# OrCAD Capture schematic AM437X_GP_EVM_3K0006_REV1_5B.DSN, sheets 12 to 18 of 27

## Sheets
12 Pg14: Camera #0: size C; rev: 1.5A
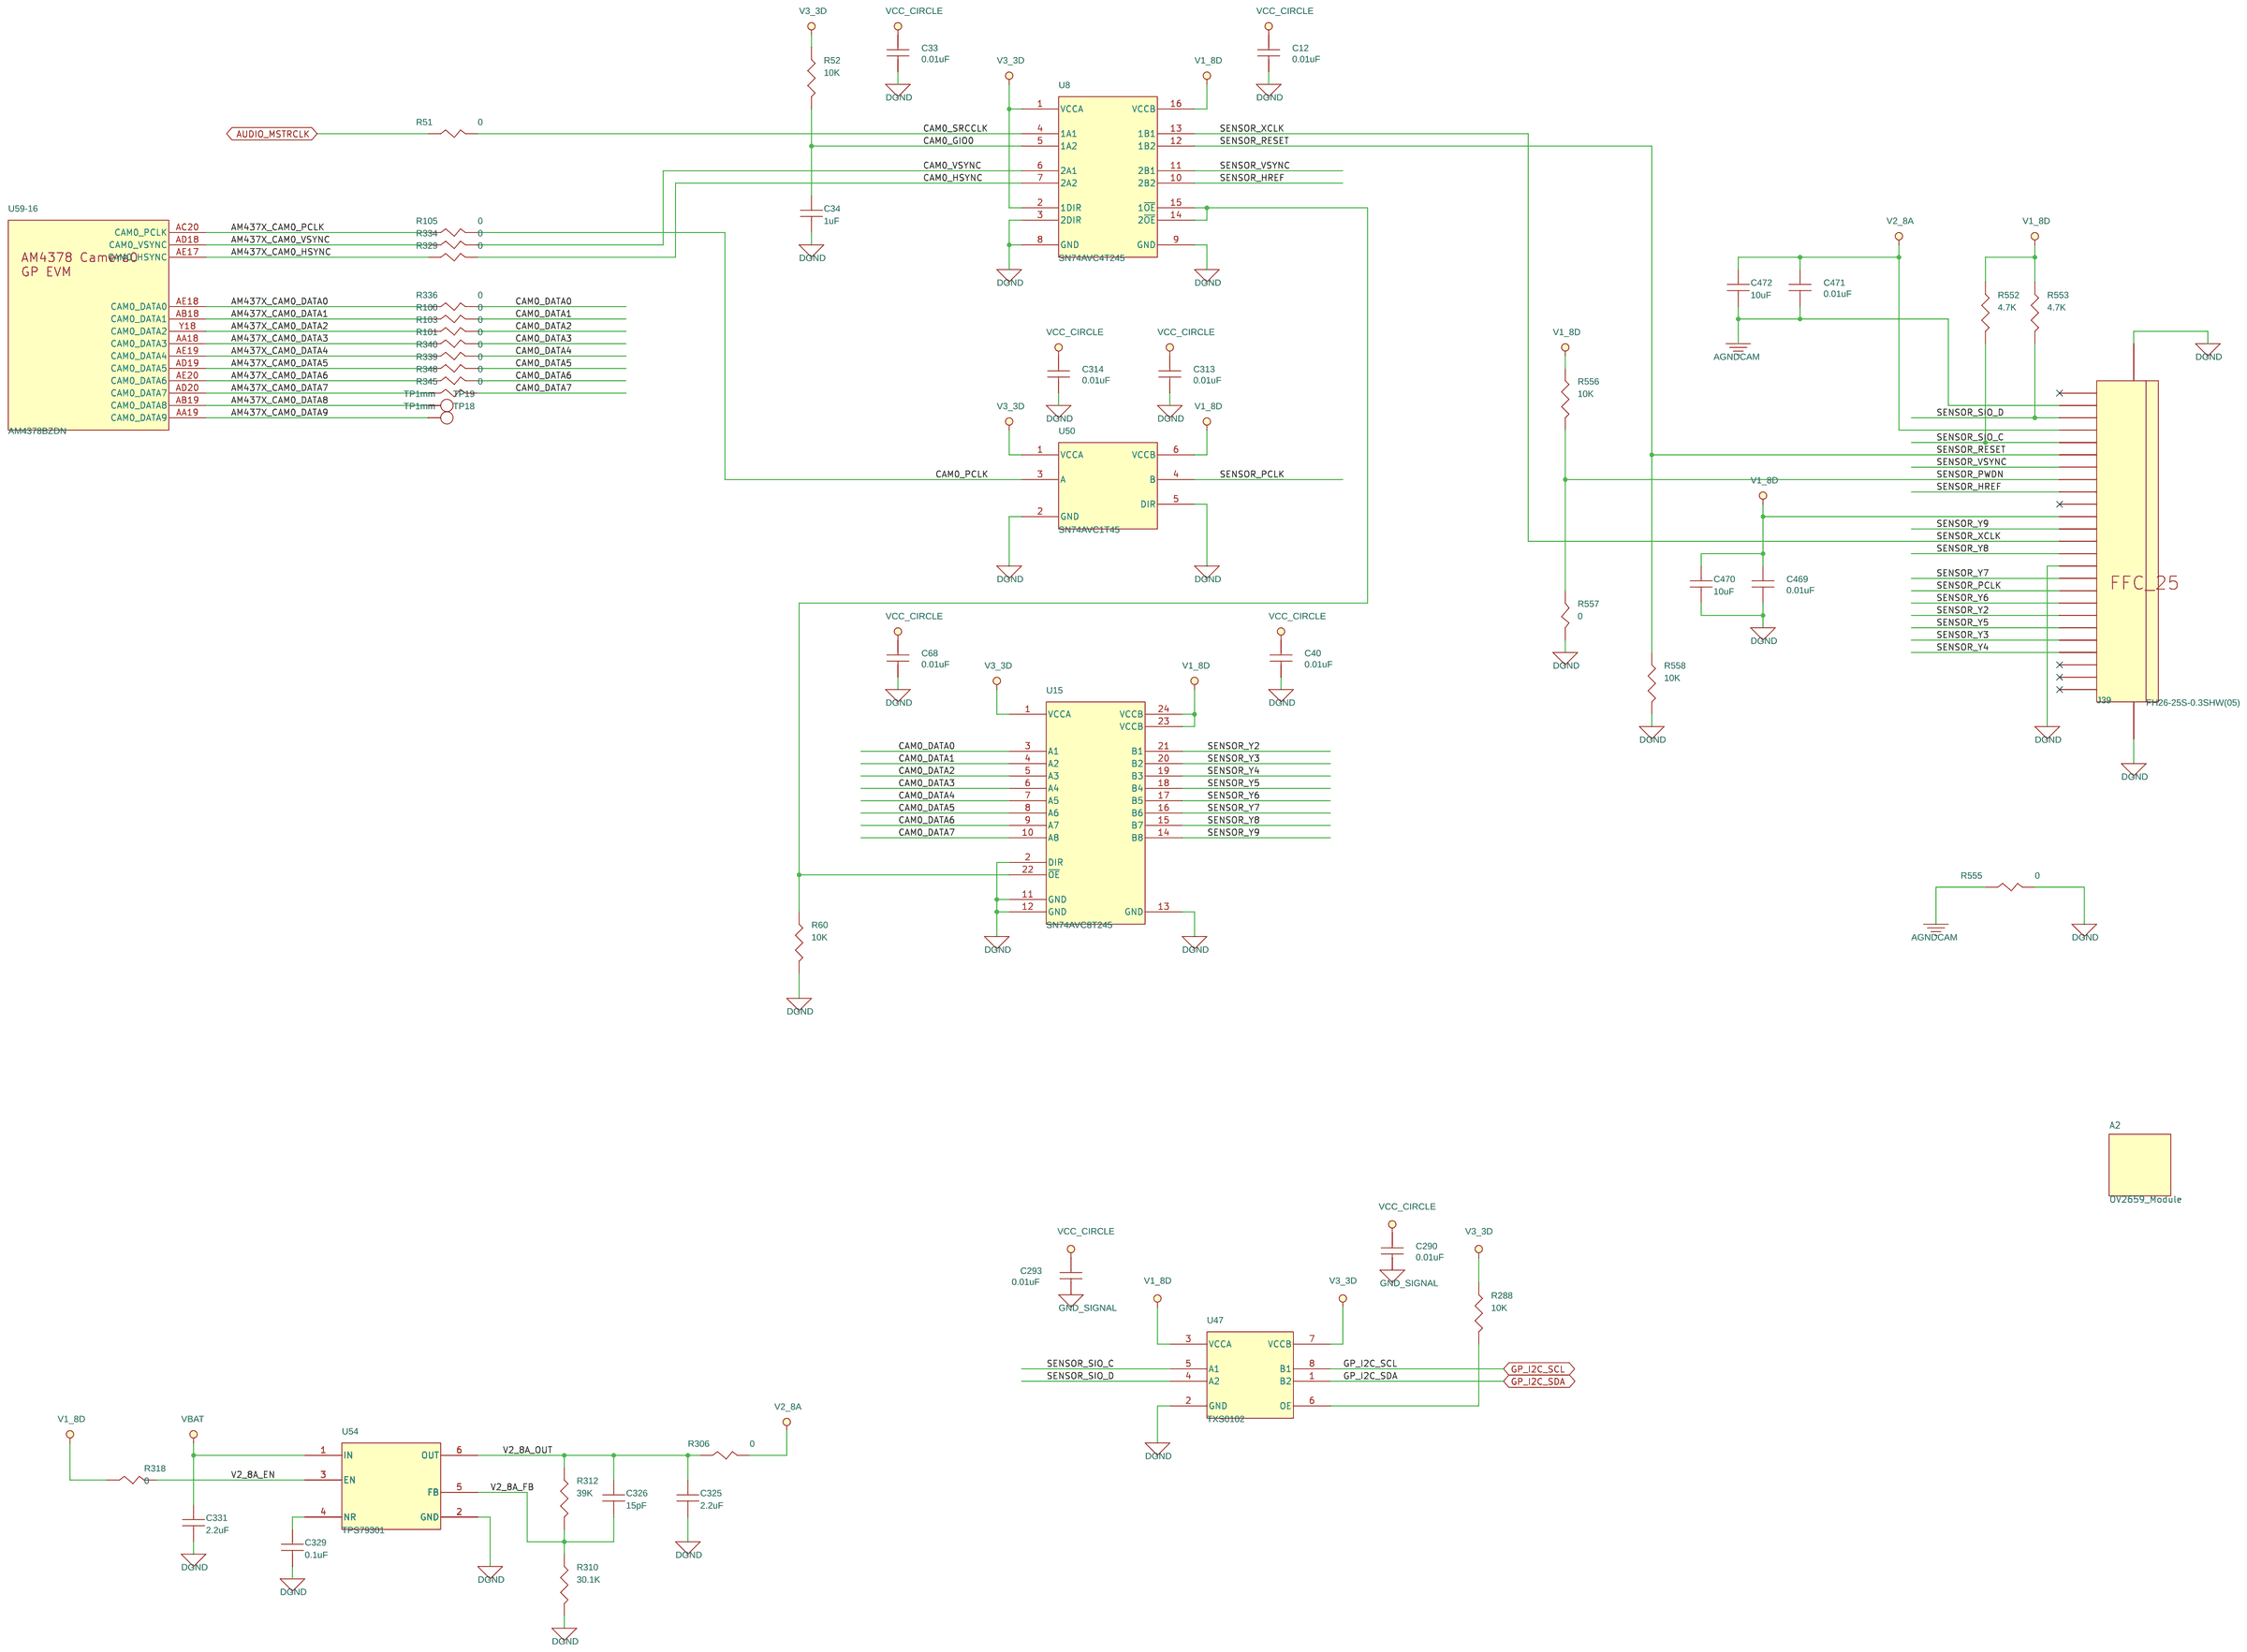
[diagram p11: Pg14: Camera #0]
13 Pg01: Title Page: note: Preliminary
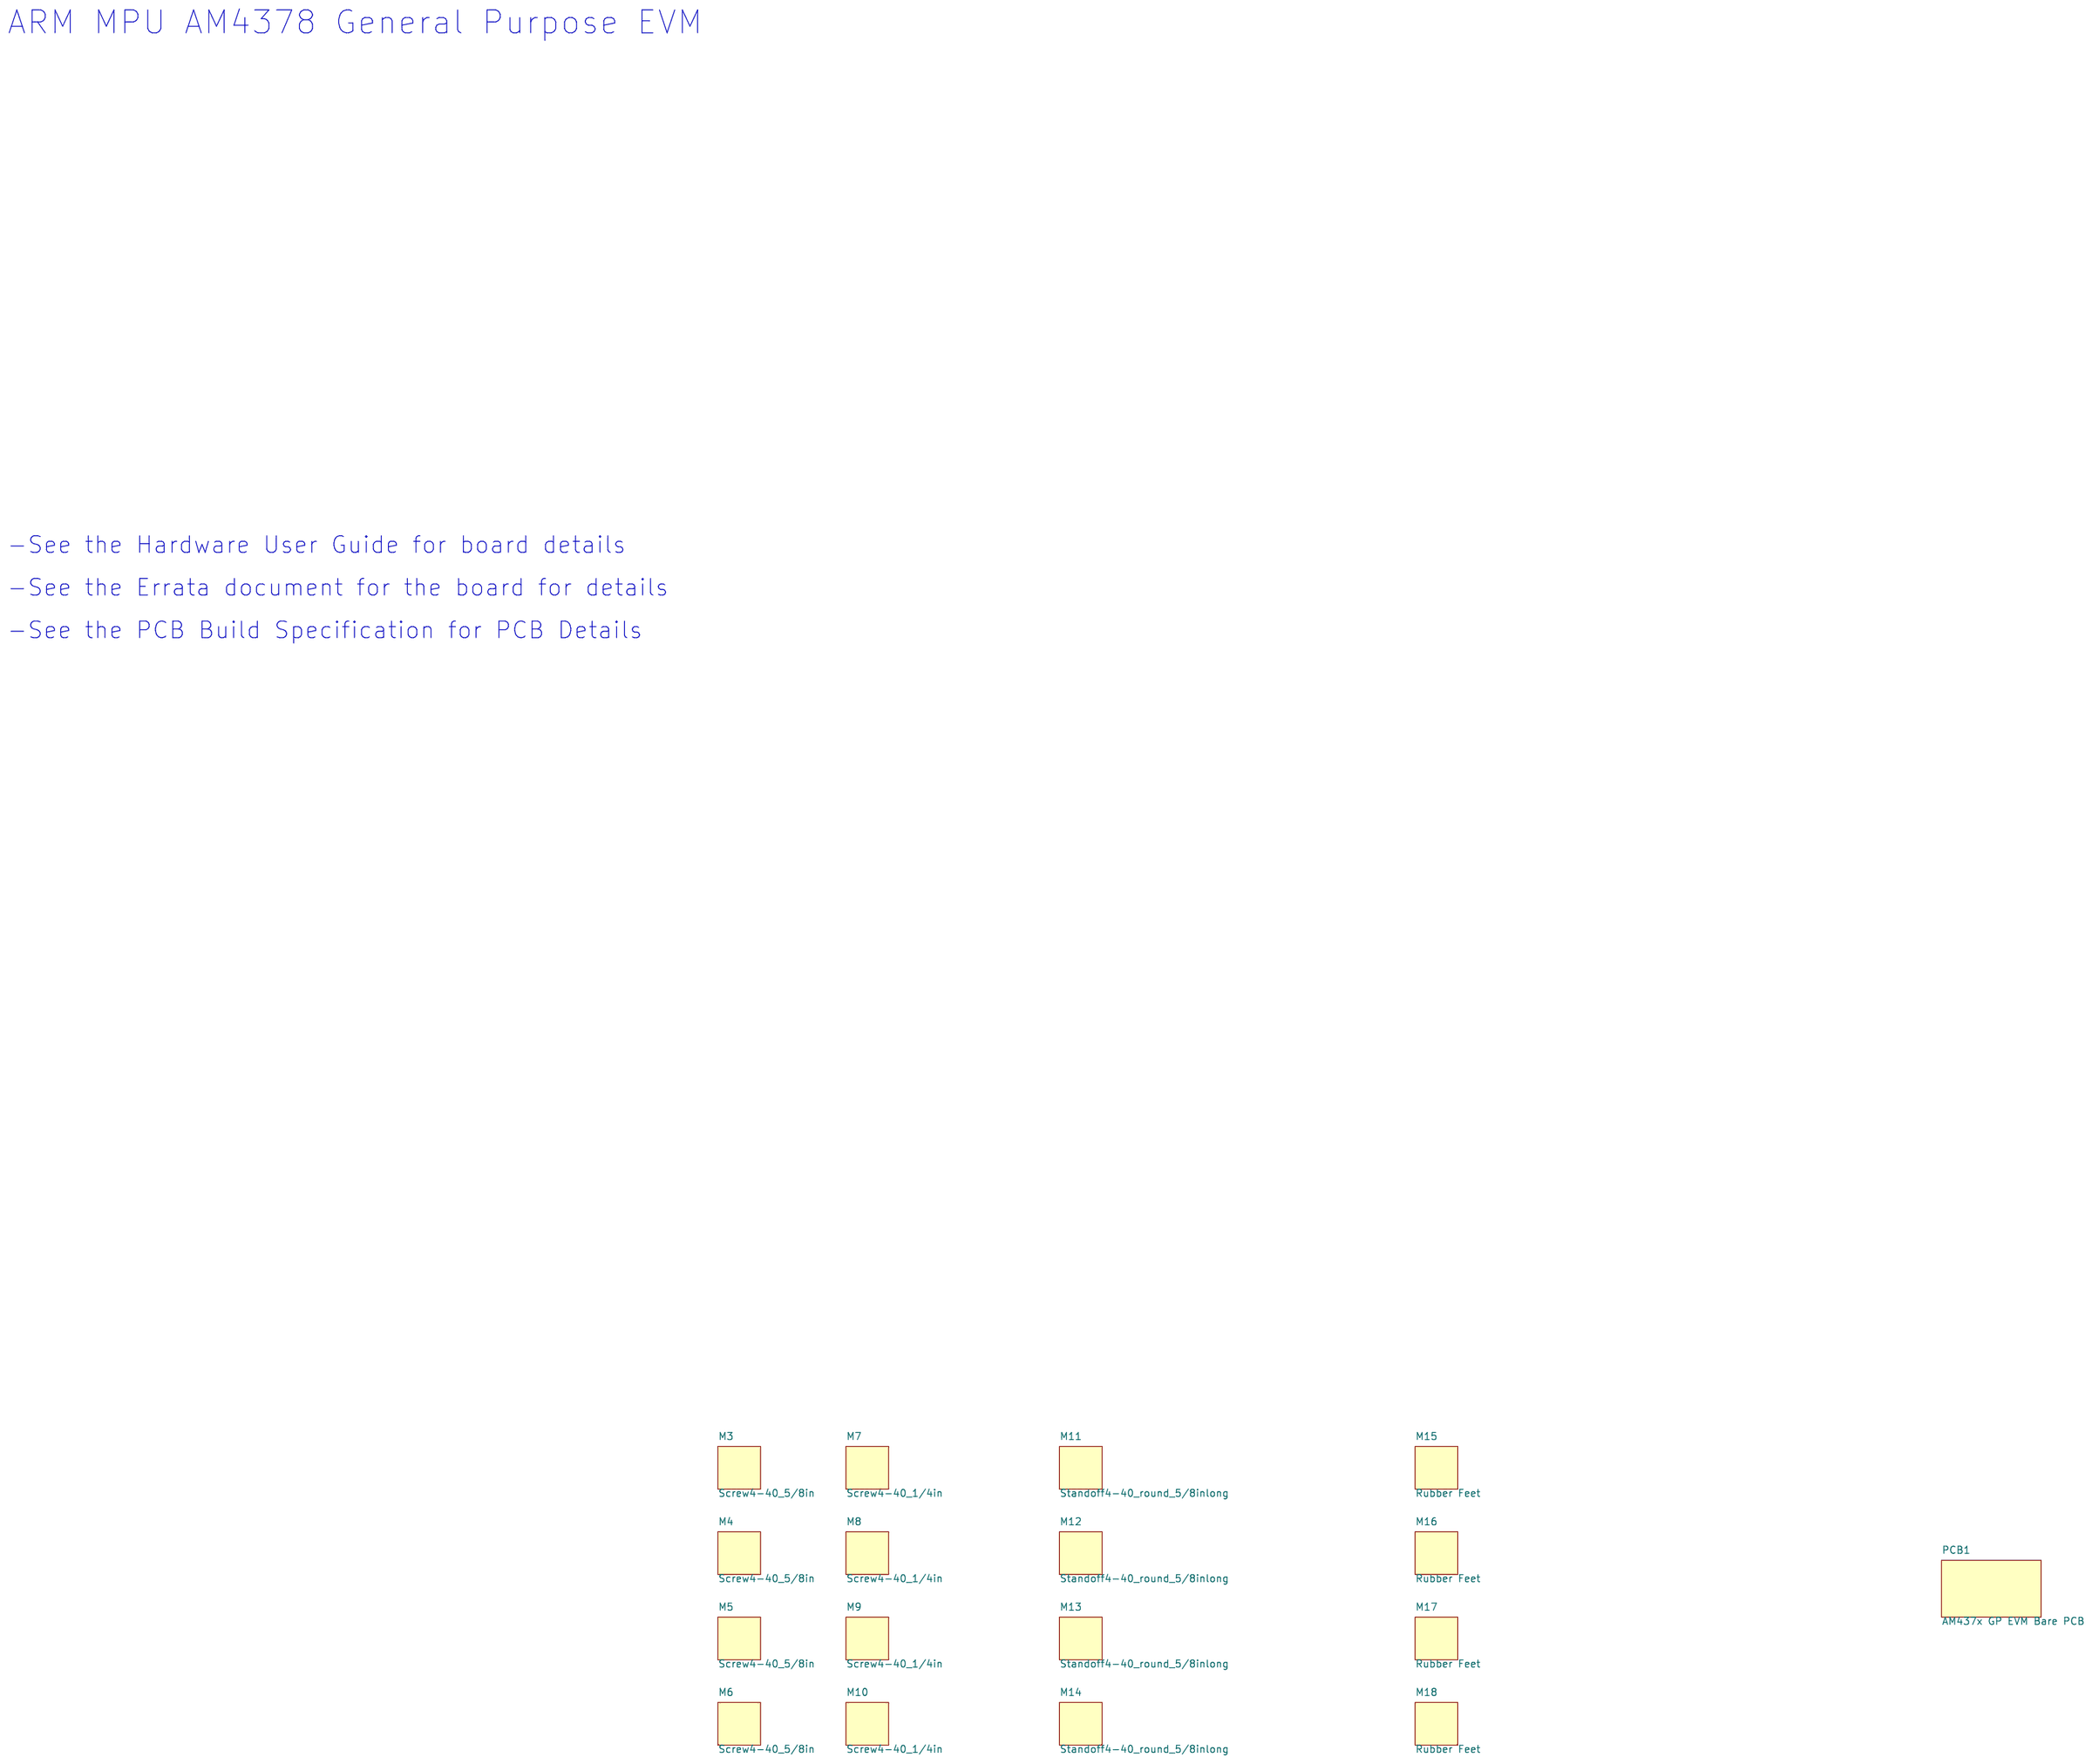
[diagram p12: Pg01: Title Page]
14 Pg07: Ethernet #1: size C
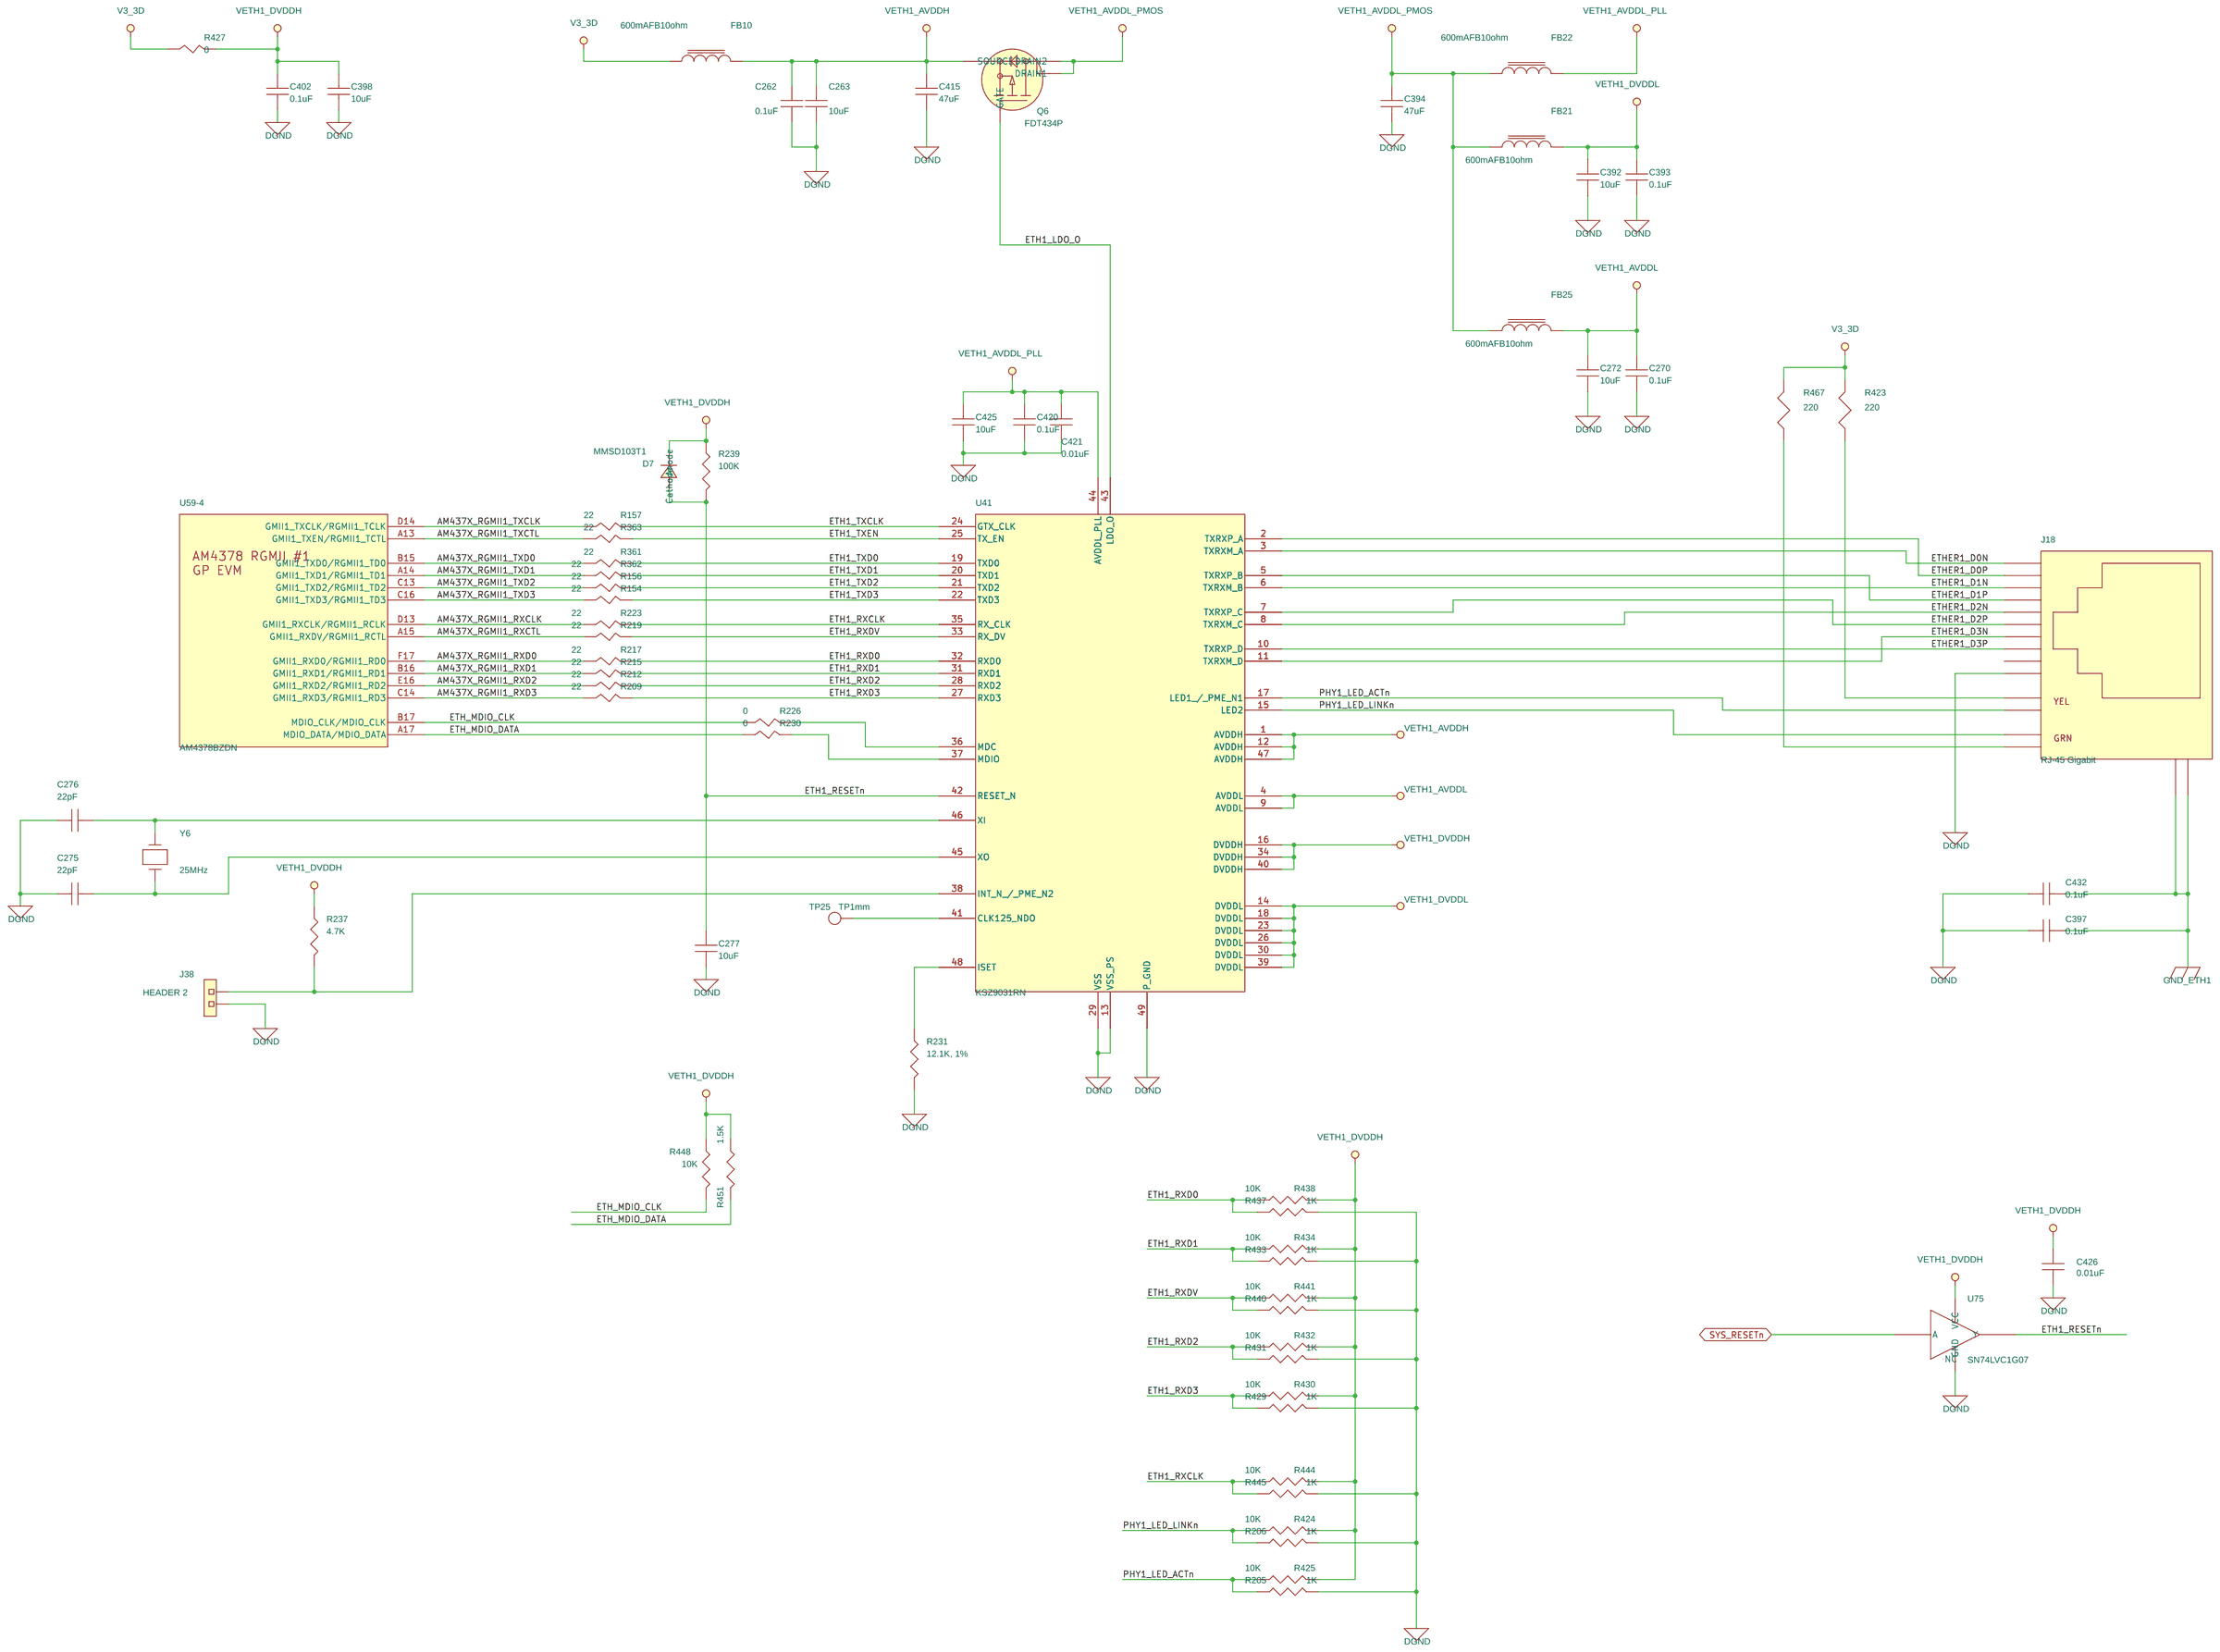
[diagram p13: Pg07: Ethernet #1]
15 Pg06: DDR3 Memory: size C
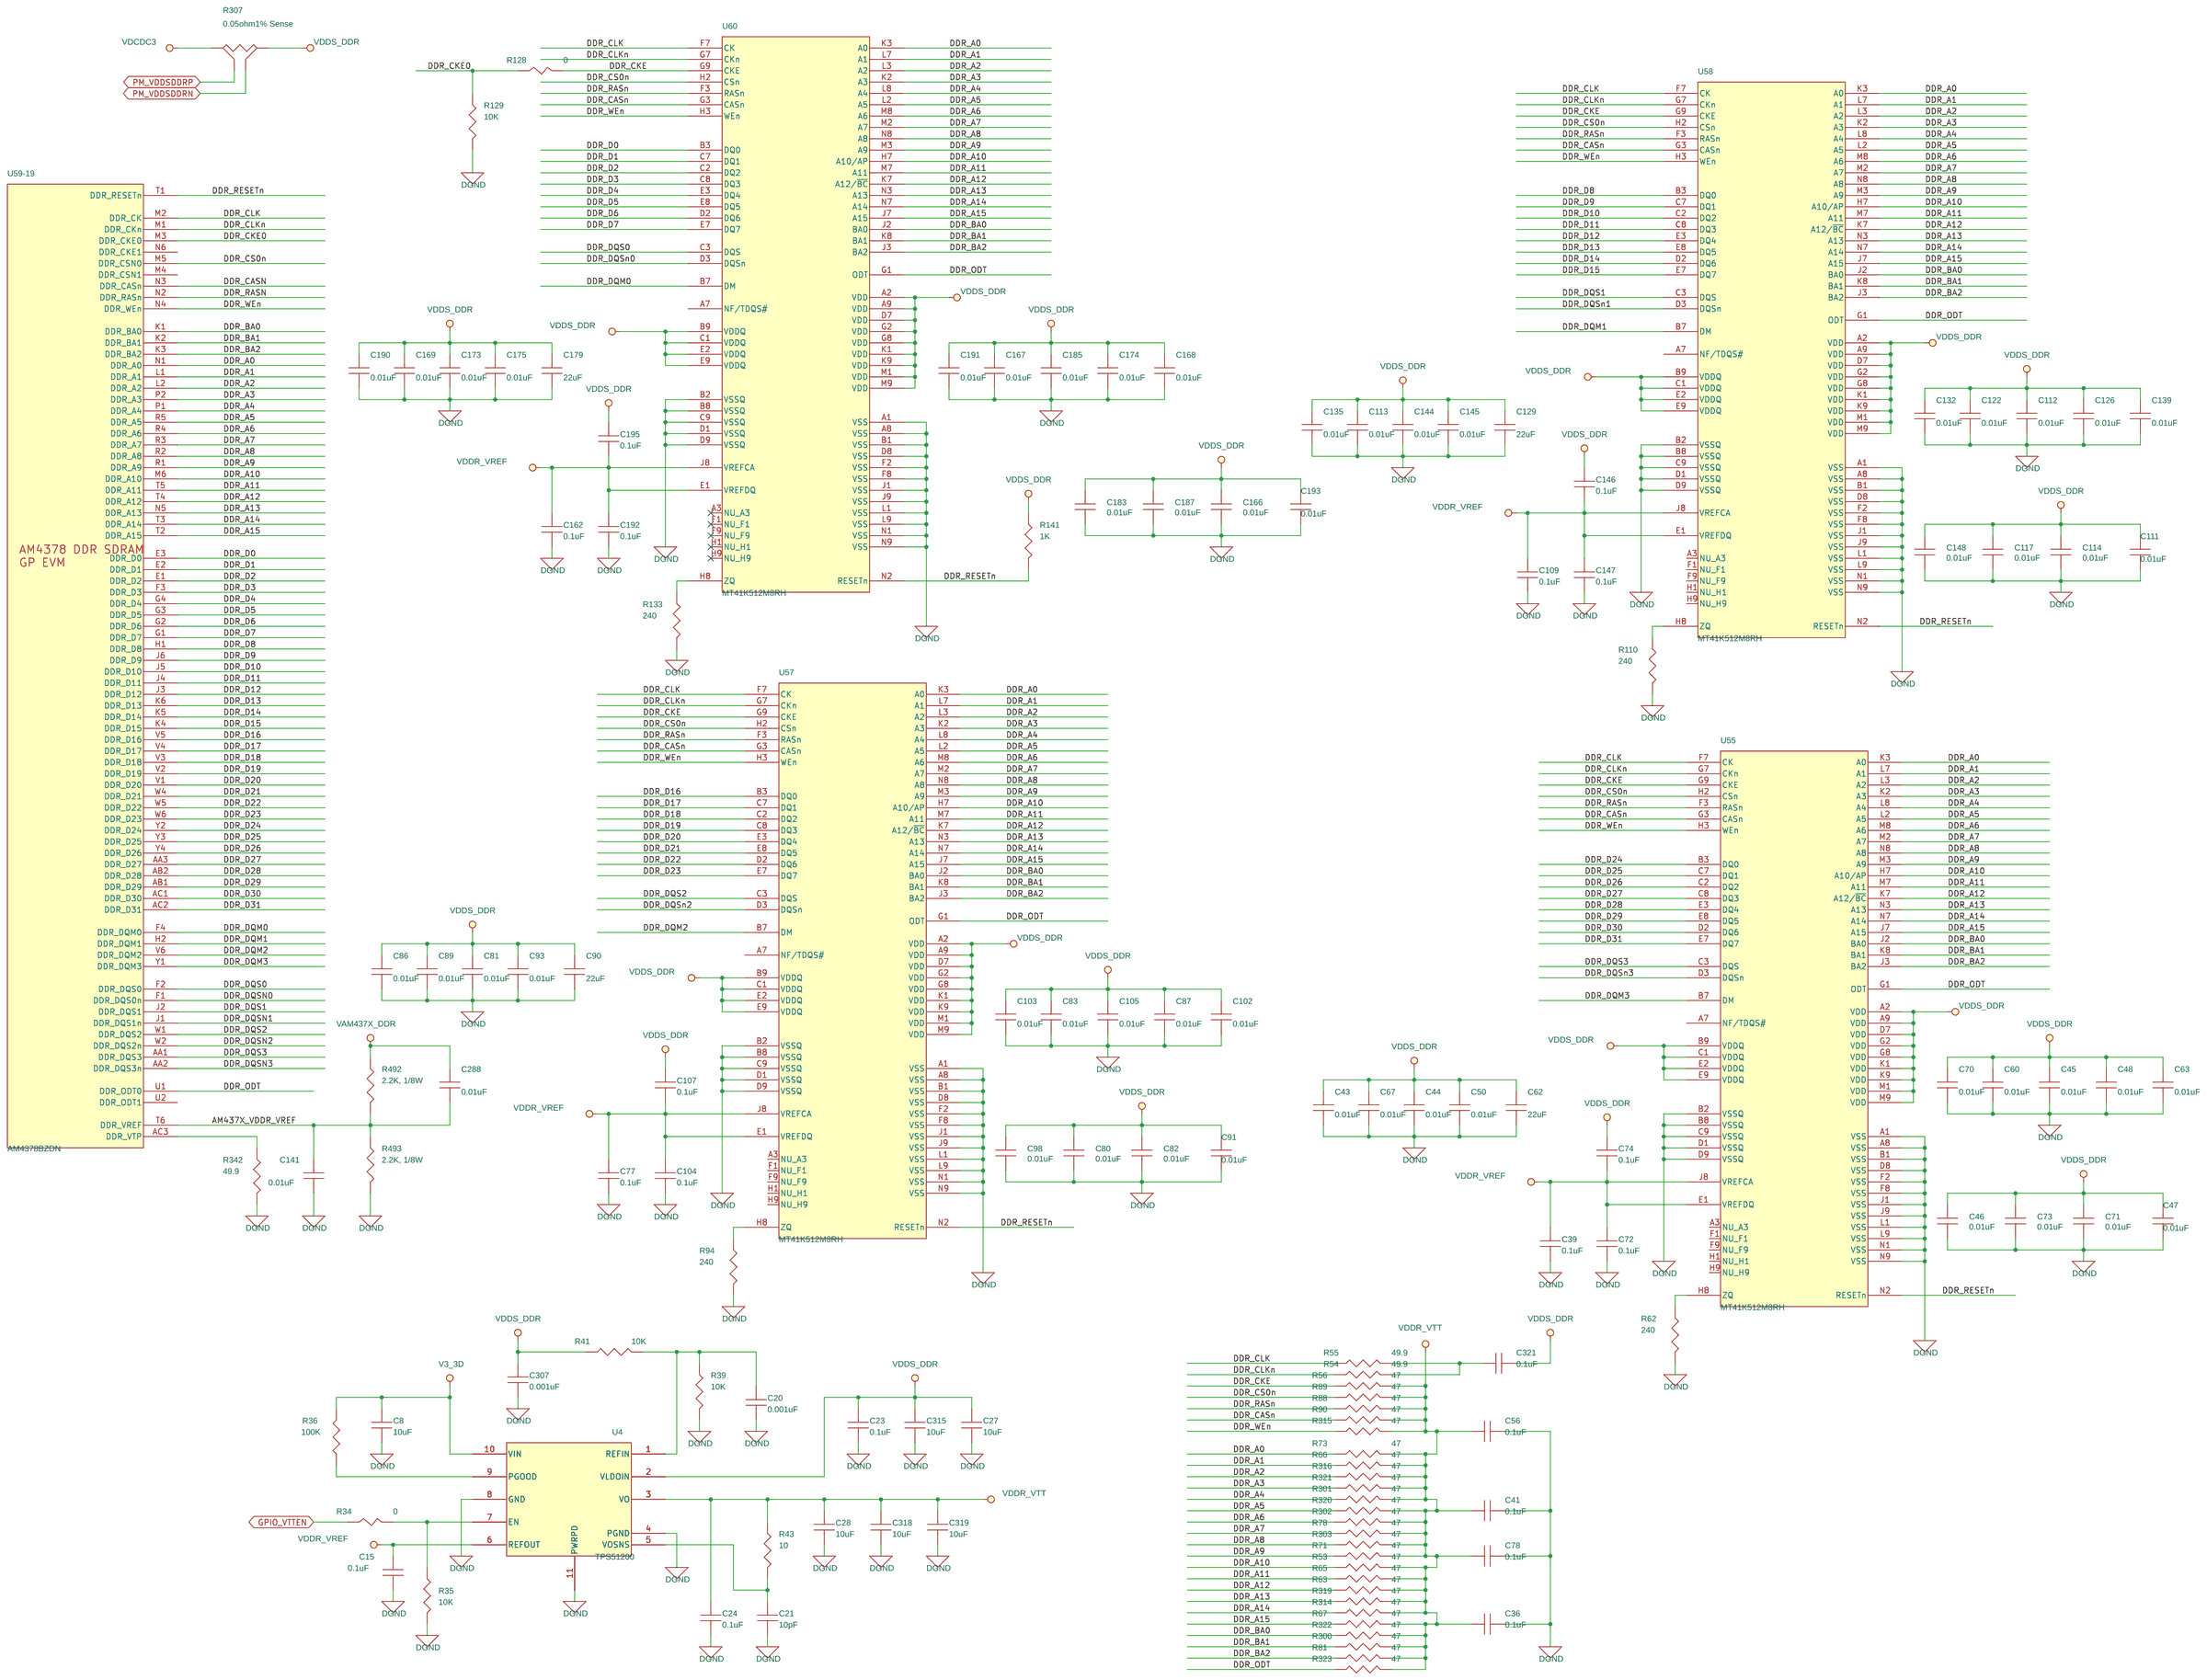
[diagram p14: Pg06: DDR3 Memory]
16 Pg17: USB Port #0: size C
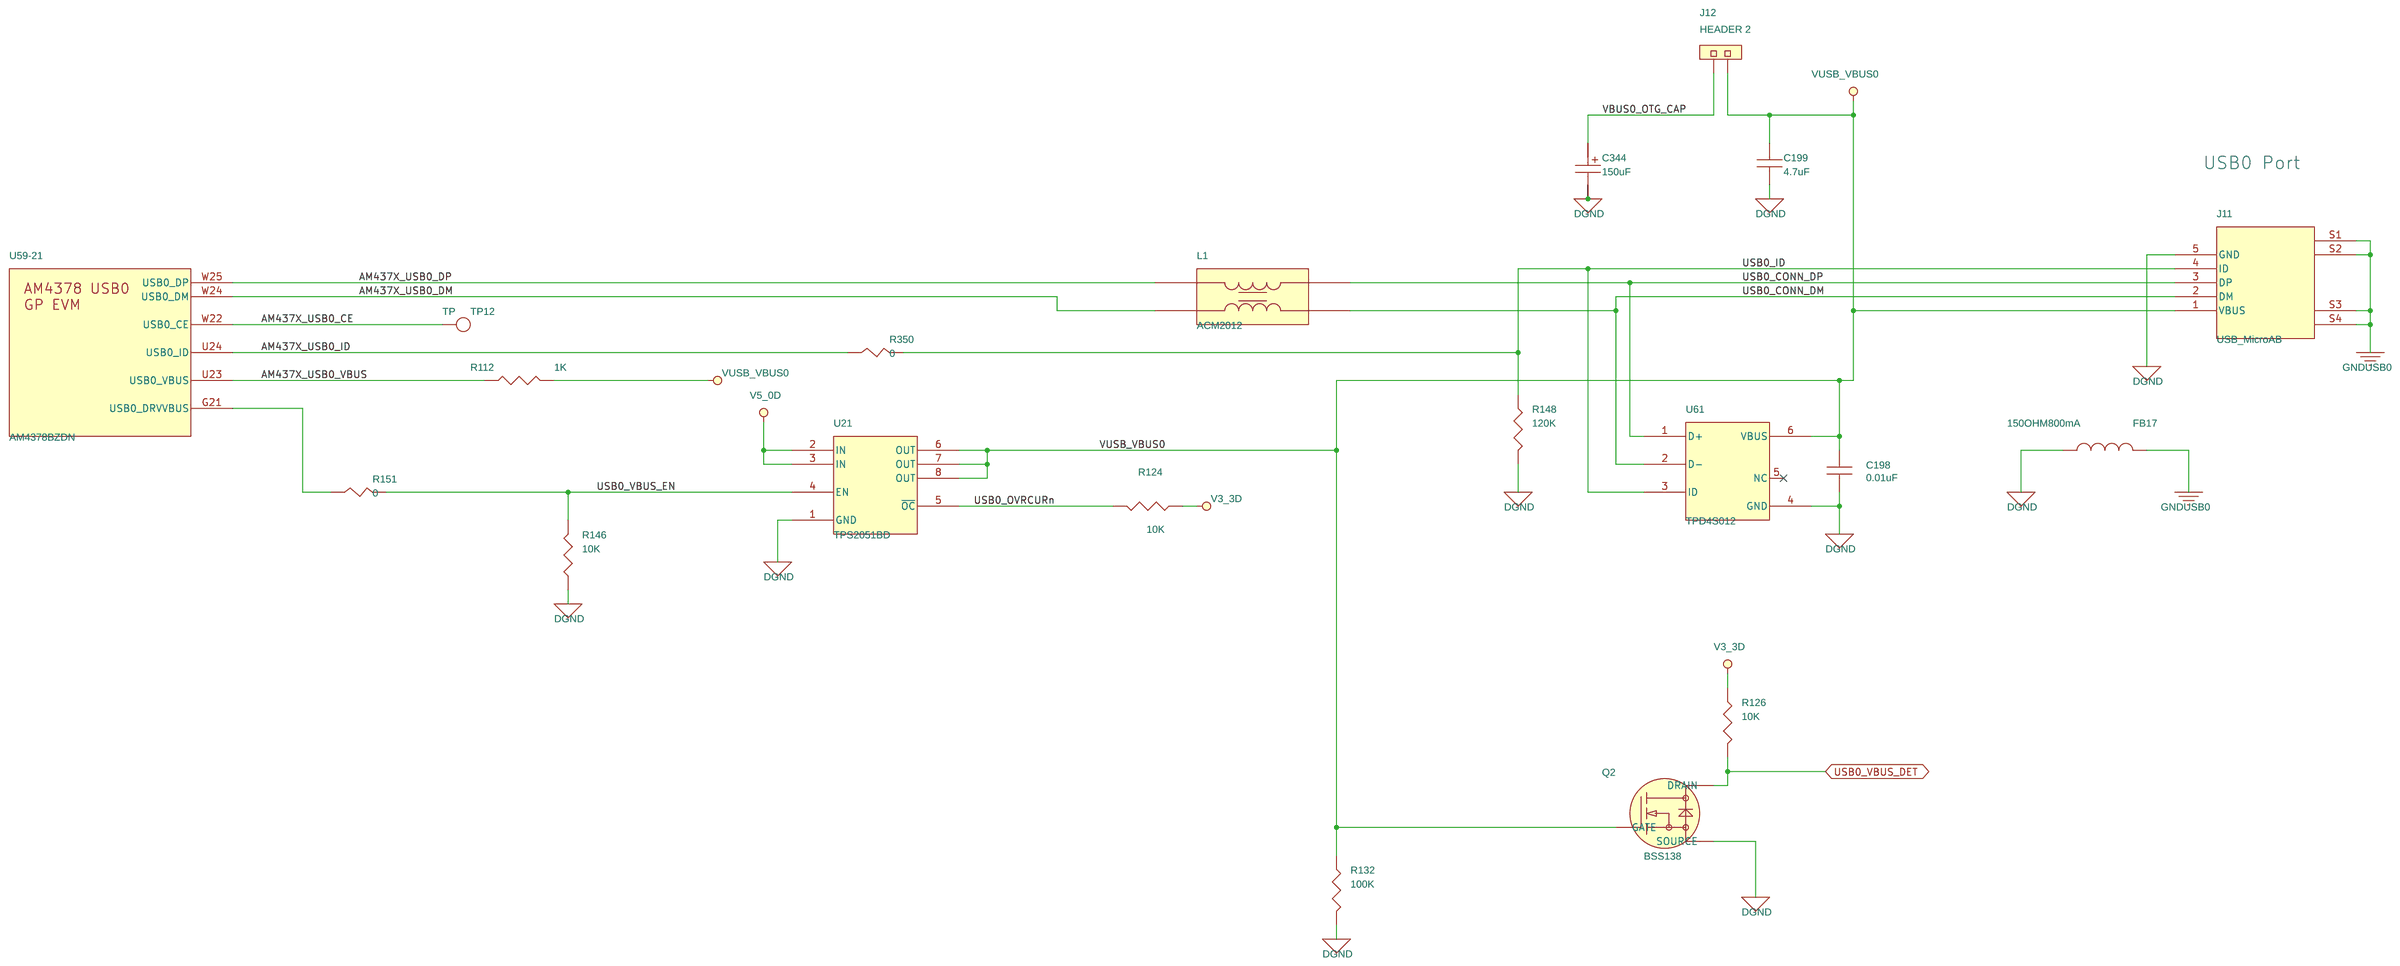
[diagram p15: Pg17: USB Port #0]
17 Pg03: Processor Power: size C
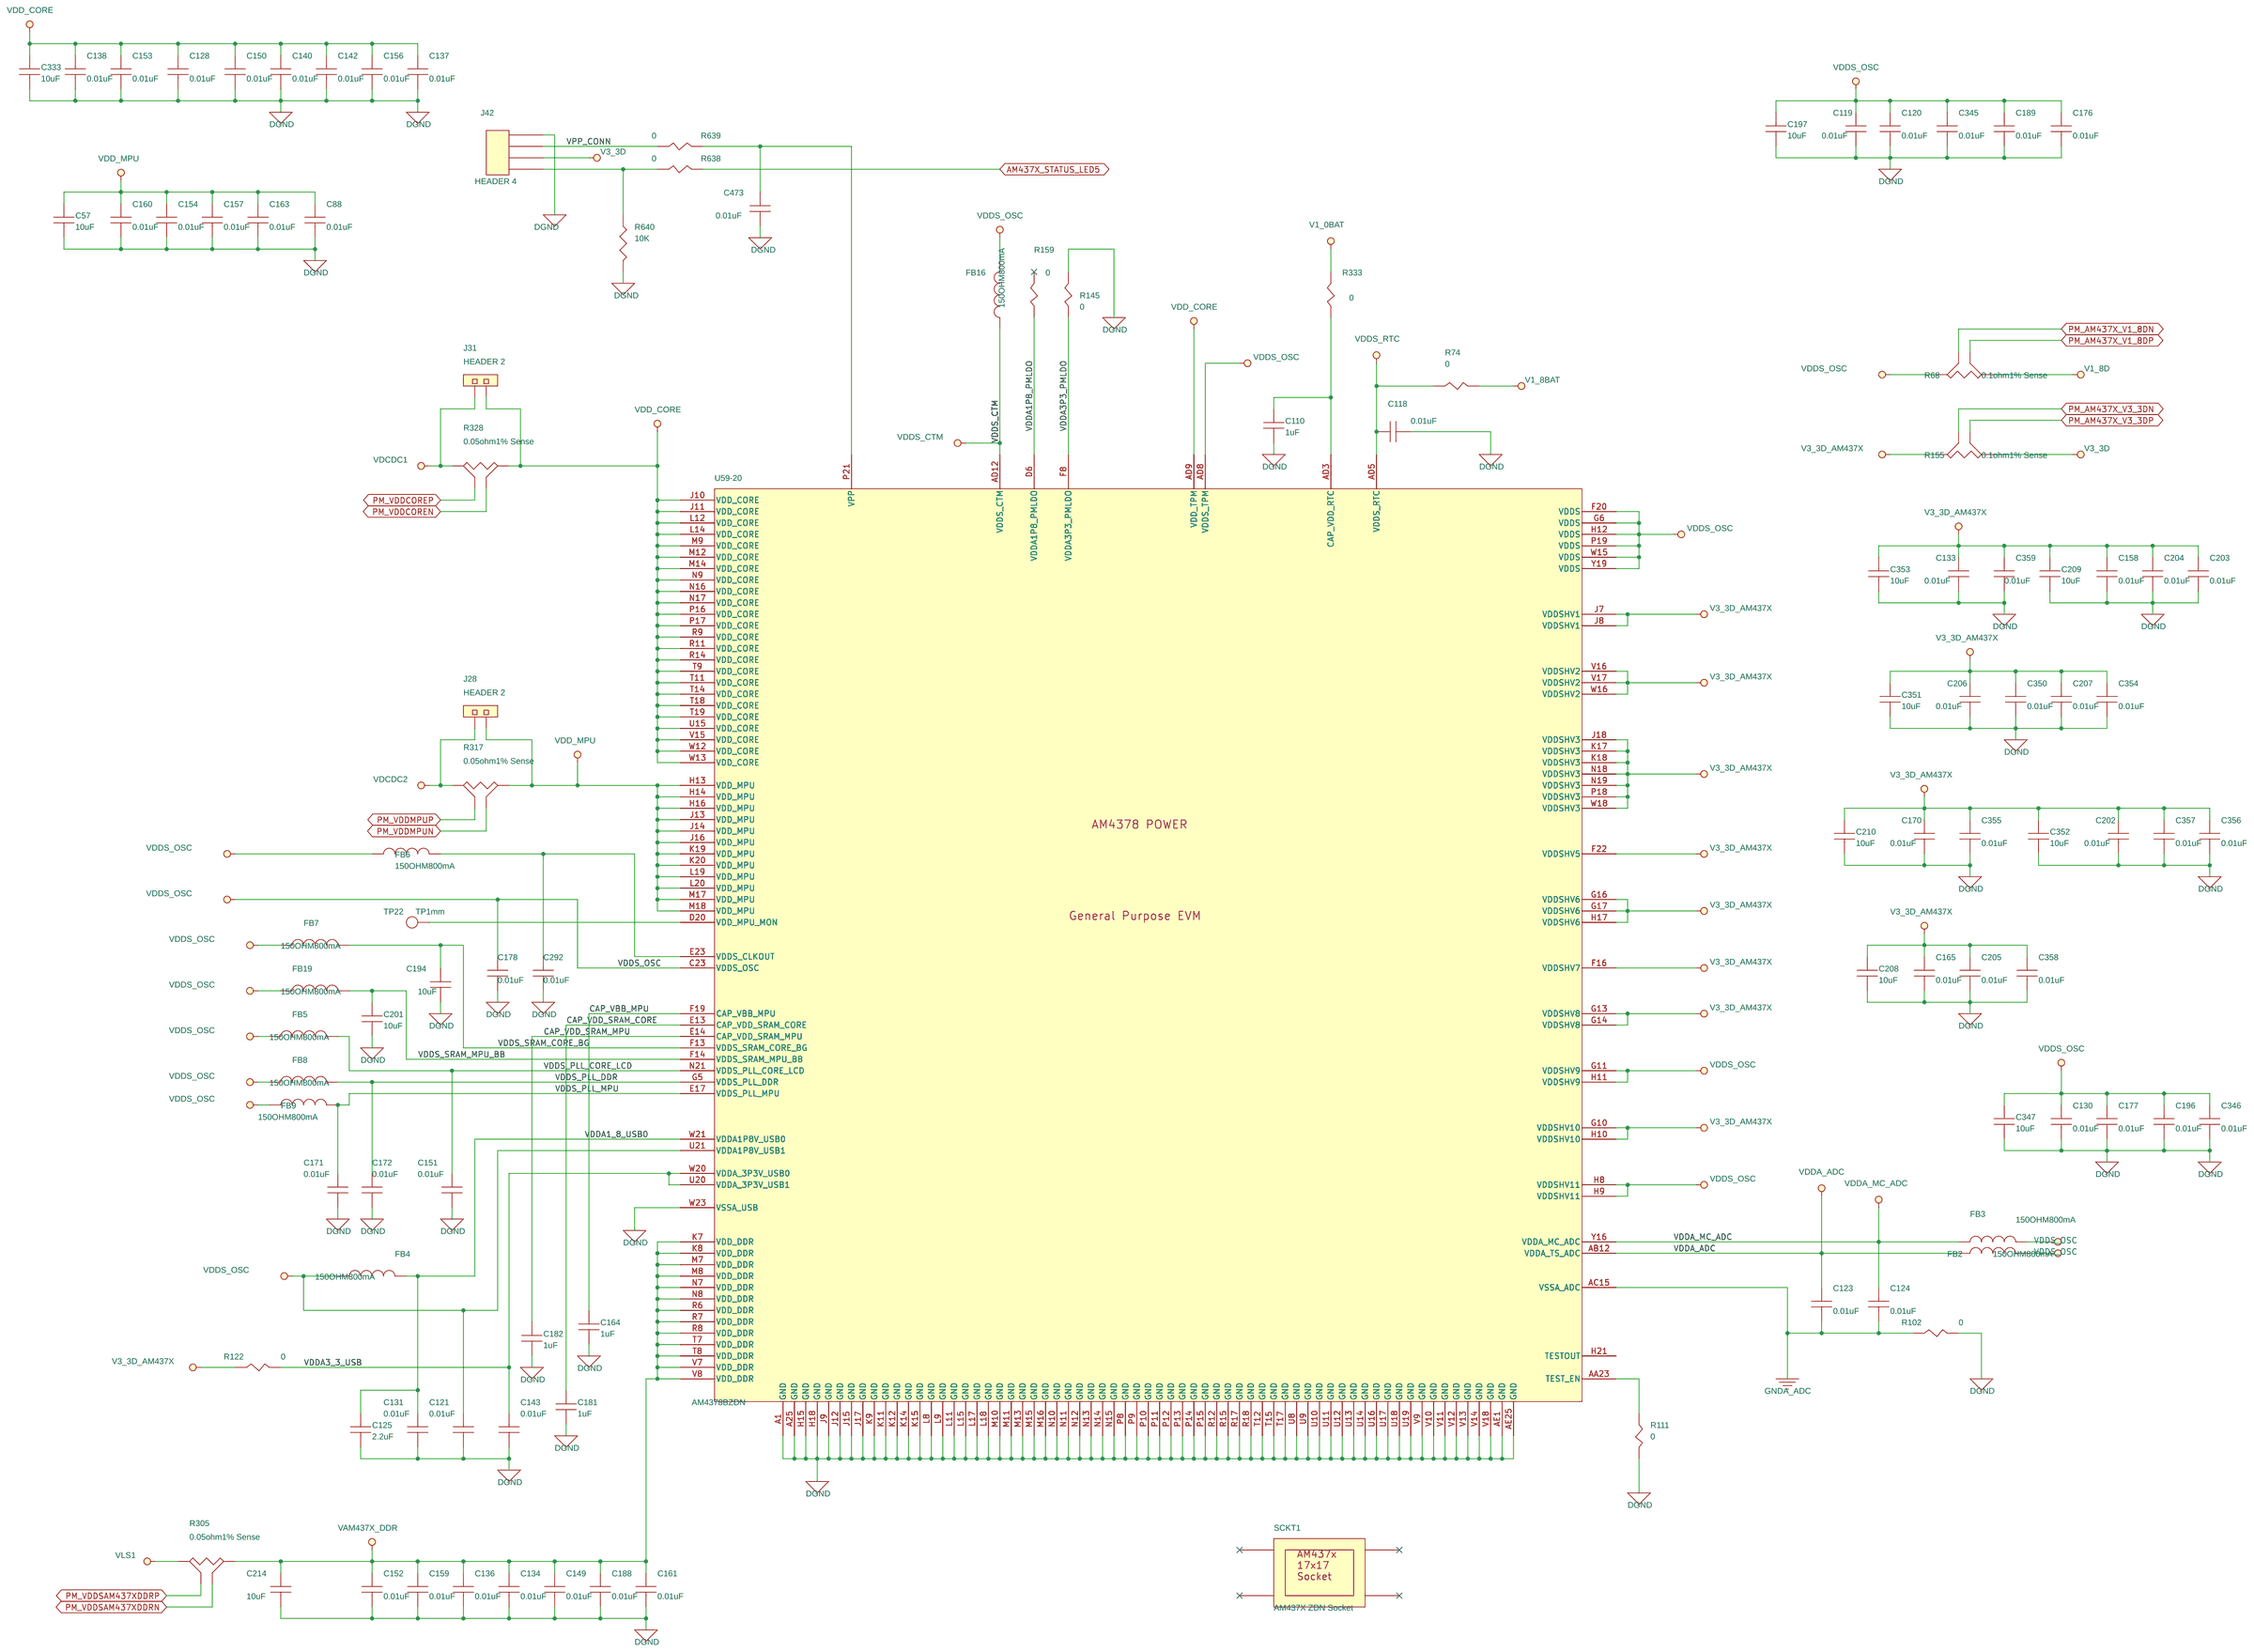
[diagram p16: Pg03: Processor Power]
18 Pg19: Wireless COM8: size C
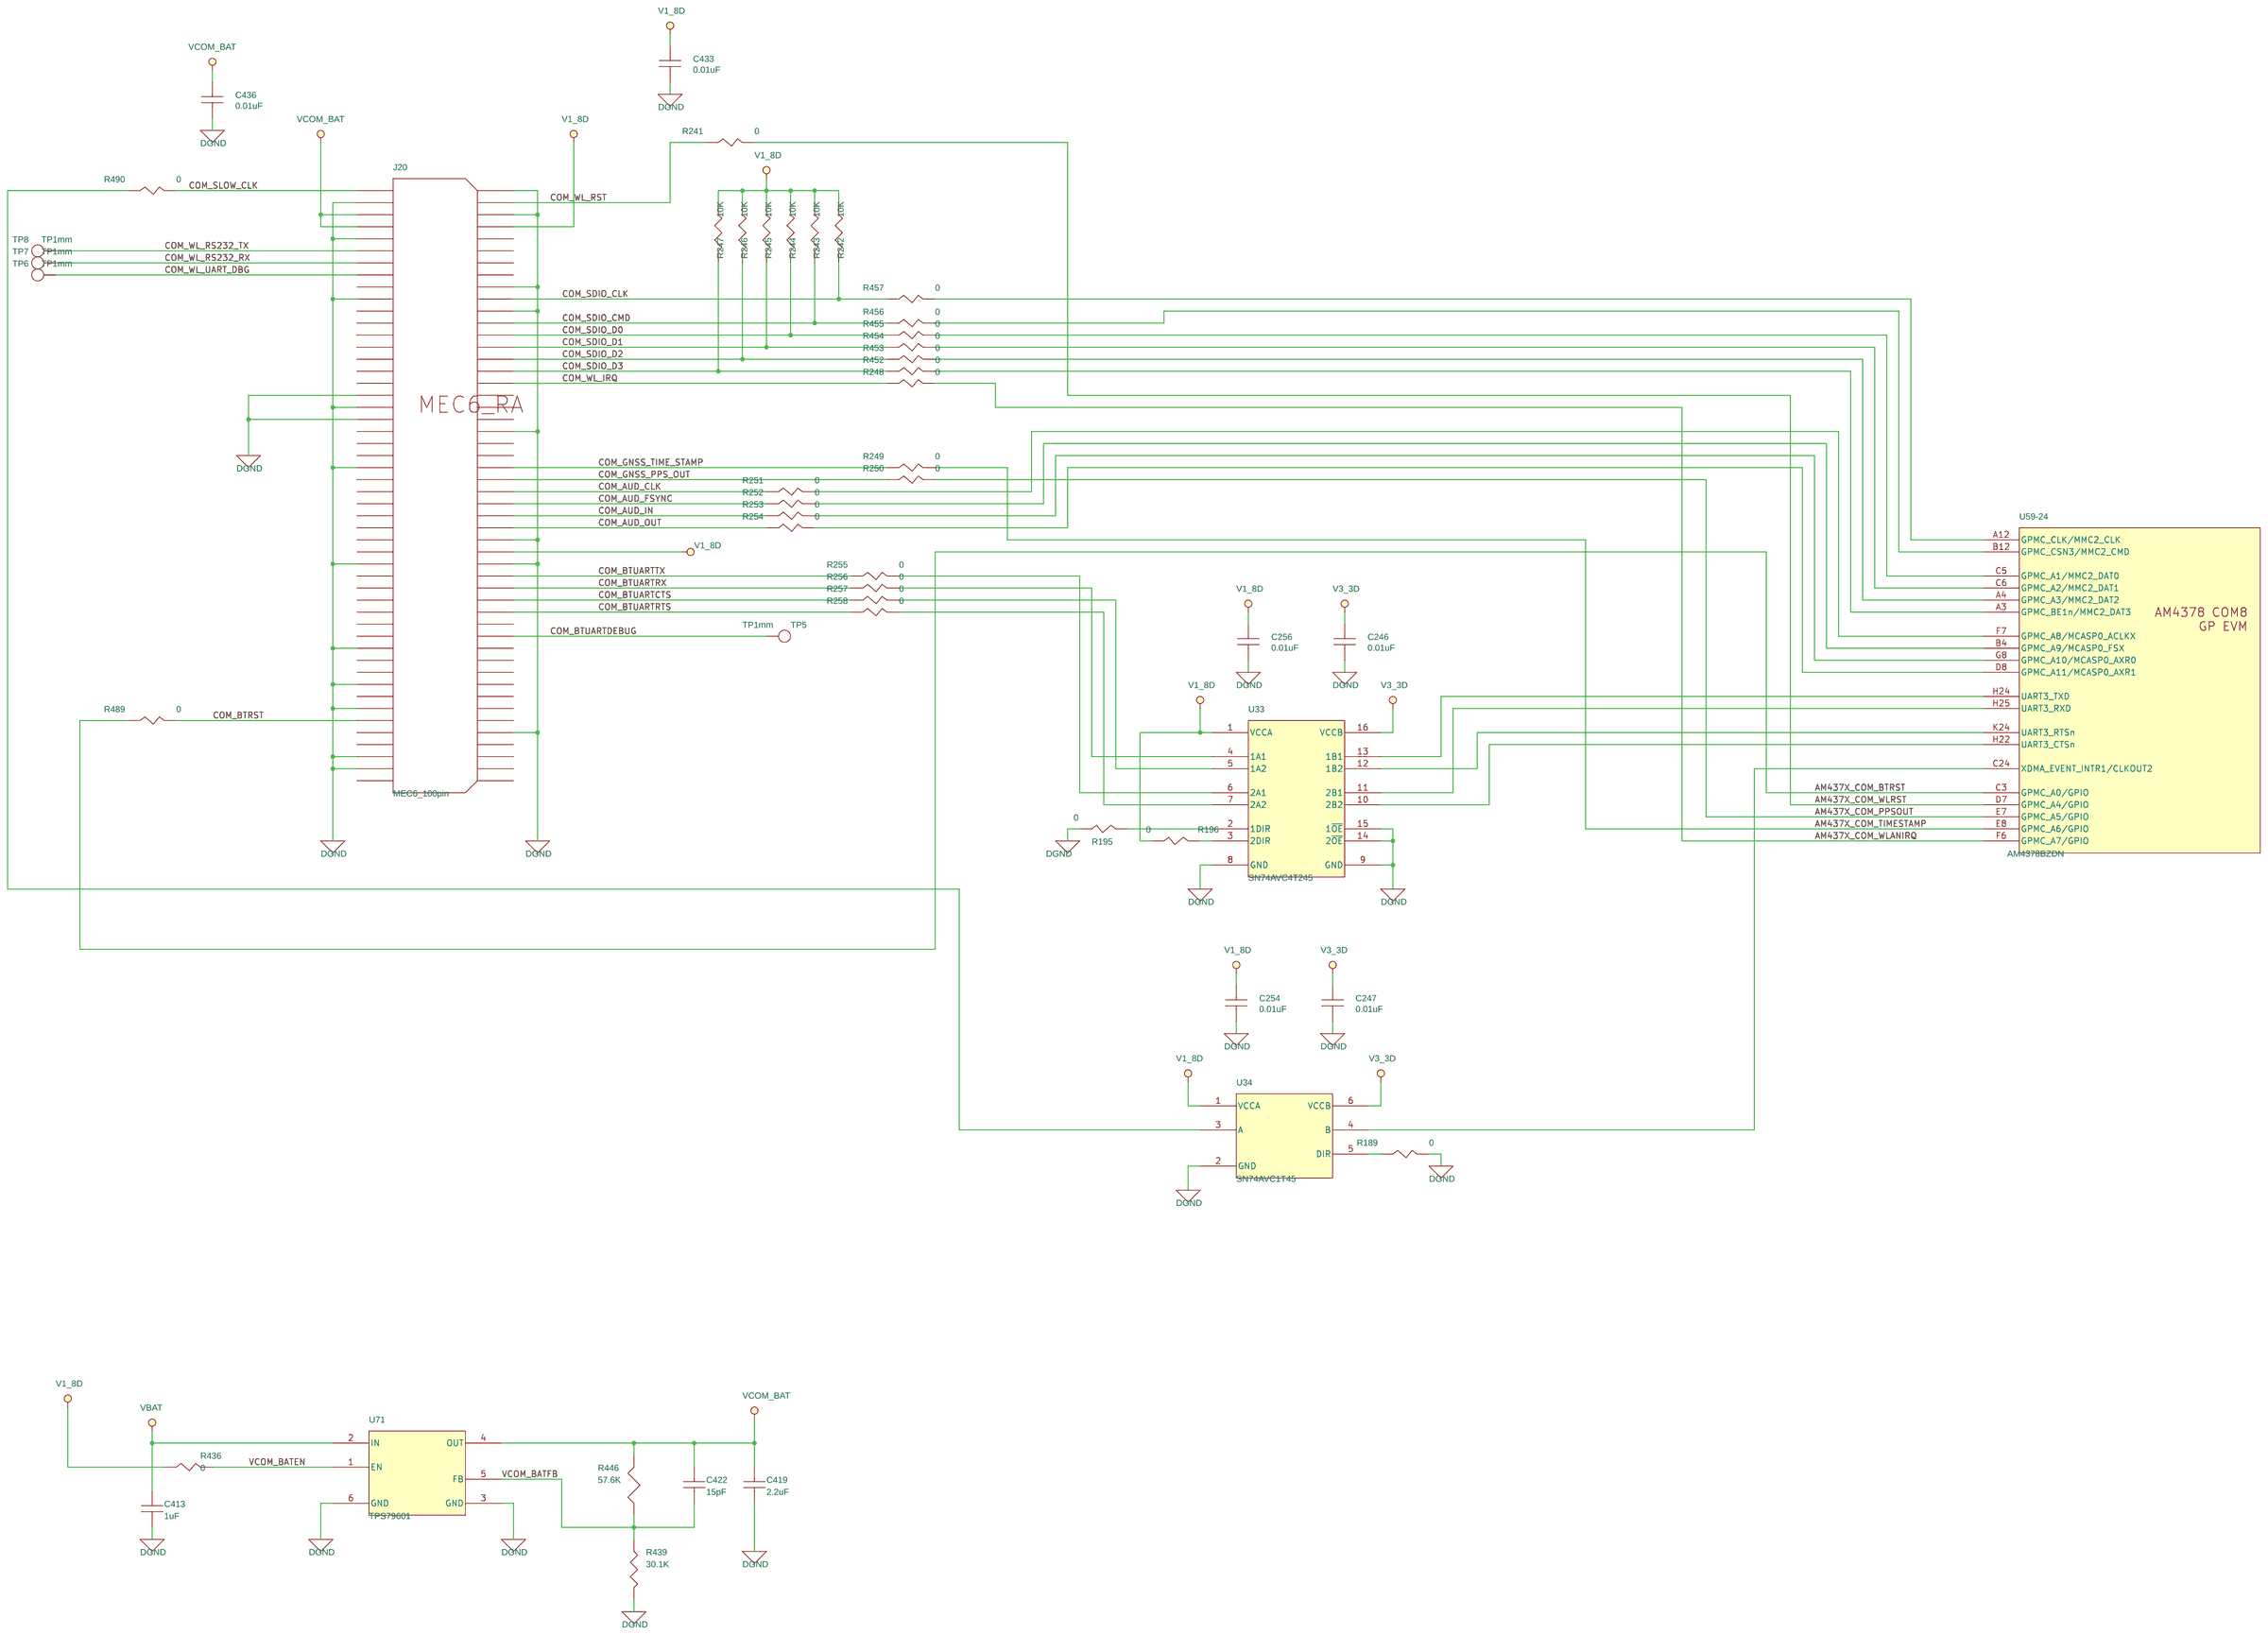
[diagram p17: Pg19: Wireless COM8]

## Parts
sheet Pg01: Title Page
M3  Screw4-40_5/8in  [DNP]
M4  Screw4-40_5/8in  [DNP]
M5  Screw4-40_5/8in  [DNP]
M6  Screw4-40_5/8in  [DNP]
M7  Screw4-40_1/4in  [DNP]
M8  Screw4-40_1/4in  [DNP]
M9  Screw4-40_1/4in  [DNP]
M10  Screw4-40_1/4in  [DNP]
M11  Standoff4-40_round_5/8inlong  [DNP]
M12  Standoff4-40_round_5/8inlong  [DNP]
M13  Standoff4-40_round_5/8inlong  [DNP]
M14  Standoff4-40_round_5/8inlong  [DNP]
M15  Rubber Feet  [DNP]
M16  Rubber Feet  [DNP]
M17  Rubber Feet  [DNP]
M18  Rubber Feet  [DNP]
PCB1  AM437x GP EVM Bare PCB  [DNP]
sheet Pg03: Processor Power
C57  10uF  [SM-7351-CAP-0805]
C88  0.01uF  [SM-7351-CAP-0402]
C110  1uF  [SM-7351-CAP-0402]
C118  0.01uF  [SM-7351-CAP-0402]
C119  0.01uF  [SM-7351-CAP-0402]
C120  0.01uF  [SM-7351-CAP-0402]
C121  0.01uF  [SM-7351-CAP-0402]
C123  0.01uF  [SM-7351-CAP-0402]
C124  0.01uF  [SM-7351-CAP-0402]
C125  2.2uF  [SM-7351-CAP-0805]
C128  0.01uF  [SM-7351-CAP-0402]
C130  0.01uF  [SM-7351-CAP-0402]
C131  0.01uF  [SM-7351-CAP-0402]
C133  0.01uF  [SM-7351-CAP-0402]
C134  0.01uF  [SM-7351-CAP-0402]
C136  0.01uF  [SM-7351-CAP-0402]
C137  0.01uF  [SM-7351-CAP-0402]
C138  0.01uF  [SM-7351-CAP-0402]
C140  0.01uF  [SM-7351-CAP-0402]
C142  0.01uF  [SM-7351-CAP-0402]
C143  0.01uF  [SM-7351-CAP-0402]
C149  0.01uF  [SM-7351-CAP-0402]
C150  0.01uF  [SM-7351-CAP-0402]
C151  0.01uF  [SM-7351-CAP-0402]
C152  0.01uF  [SM-7351-CAP-0402]
C153  0.01uF  [SM-7351-CAP-0402]
C154  0.01uF  [SM-7351-CAP-0402]
C156  0.01uF  [SM-7351-CAP-0402]
C157  0.01uF  [SM-7351-CAP-0402]
C158  0.01uF  [SM-7351-CAP-0402]
C159  0.01uF  [SM-7351-CAP-0402]
C160  0.01uF  [SM-7351-CAP-0402]
C161  0.01uF  [SM-7351-CAP-0402]
C163  0.01uF  [SM-7351-CAP-0402]
C164  1uF  [SM-7351-CAP-0402]
C165  0.01uF  [SM-7351-CAP-0402]
C170  0.01uF  [SM-7351-CAP-0402]
C171  0.01uF  [SM-7351-CAP-0402]
C172  0.01uF  [SM-7351-CAP-0402]
C176  0.01uF  [SM-7351-CAP-0402]
C177  0.01uF  [SM-7351-CAP-0402]
C178  0.01uF  [SM-7351-CAP-0402]
C181  1uF  [SM-7351-CAP-0402]
C182  1uF  [SM-7351-CAP-0402]
C188  0.01uF  [SM-7351-CAP-0402]
C189  0.01uF  [SM-7351-CAP-0402]
C194  10uF  [SM-7351-CAP-0603]
C196  0.01uF  [SM-7351-CAP-0402]
C197  10uF  [SM-7351-CAP-0805]
C201  10uF  [SM-7351-CAP-0603]
C202  0.01uF  [SM-7351-CAP-0402]
C203  0.01uF  [SM-7351-CAP-0402]
C204  0.01uF  [SM-7351-CAP-0402]
C205  0.01uF  [SM-7351-CAP-0402]
C206  0.01uF  [SM-7351-CAP-0402]
C207  0.01uF  [SM-7351-CAP-0402]
C208  10uF  [SM-7351-CAP-0805]
C209  10uF  [SM-7351-CAP-0805]
C210  10uF  [SM-7351-CAP-0805]
C214  10uF  [SM-7351-CAP-0805]
C292  0.01uF  [SM-7351-CAP-0402]
C333  10uF  [SM-7351-CAP-0805]
C345  0.01uF  [SM-7351-CAP-0402]
C346  0.01uF  [SM-7351-CAP-0402]
C347  10uF  [SM-7351-CAP-0805]
C350  0.01uF  [SM-7351-CAP-0402]
C351  10uF  [SM-7351-CAP-0805]
C352  10uF  [SM-7351-CAP-0805]
C353  10uF  [SM-7351-CAP-0805]
C354  0.01uF  [SM-7351-CAP-0402]
C355  0.01uF  [SM-7351-CAP-0402]
C356  0.01uF  [SM-7351-CAP-0402]
C357  0.01uF  [SM-7351-CAP-0402]
C358  0.01uF  [SM-7351-CAP-0402]
C359  0.01uF  [SM-7351-CAP-0402]
C473  0.01uF  [SM-7351-CAP-0402]
FB2  150OHM800mA  [sm-7351-ind-0805]
FB3  150OHM800mA  [sm-7351-ind-0805]
FB4  150OHM800mA  [sm-7351-ind-0805]
FB5  150OHM800mA  [sm-7351-ind-0805]
FB6  150OHM800mA  [sm-7351-ind-0805]
FB7  150OHM800mA  [sm-7351-ind-0805]
FB8  150OHM800mA  [sm-7351-ind-0805]
FB9  150OHM800mA  [sm-7351-ind-0805]
FB16  150OHM800mA  [sm-7351-ind-0805]
FB19  150OHM800mA  [sm-7351-ind-0805]
J28  HEADER 2  [header_2x1]
J31  HEADER 2  [header_2x1]
J42  HEADER 4  [HDR1x4-330M]
R68  0.1ohm1% Sense  [SM_RES_0805_KELV]
R74  0  [SM-7351-RES-0402]
R102  0  [SM-7351-RES-0402]
R111  0  [SM-7351-RES-0402]
R122  0  [SM-7351-RES-0402]
R145  0  [SM-7351-RES-0603]
R155  0.1ohm1% Sense  [SM_RES_0805_KELV]
R159  0  [SM-7351-RES-0603]
R305  0.05ohm1% Sense  [SM_RES_LVK12]
R317  0.05ohm1% Sense  [SM_RES_LVK12]
R328  0.05ohm1% Sense  [SM_RES_LVK12]
R333  0  [SM-7351-RES-0603]
R638  0  [SM-7351-RES-0402]
R639  0  [SM-7351-RES-0402]
R640  10K  [SM-7351-RES-0402]
SCKT1  AM437X ZDN Socket  [SCKBGA625]
TP22  TP1mm  [tp_smd1mmcircle]
sheet Pg06: DDR3 Memory
C8  10uF  [SM-7351-CAP-0805]
C15  0.1uF  [SM-7351-CAP-0402]
C20  0.001uF  [SM-7351-CAP-0402]
C21  10pF  [SM-7351-CAP-0402]
C23  0.1uF  [SM-7351-CAP-0402]
C24  0.1uF  [SM-7351-CAP-0402]
C27  10uF  [SM-7351-CAP-0805]
C28  10uF  [SM-7351-CAP-0805]
C36  0.1uF  [SM-7351-CAP-0402]
C39  0.1uF  [SM-7351-CAP-0402]
C41  0.1uF  [SM-7351-CAP-0402]
C43  0.01uF  [SM-7351-CAP-0402]
C44  0.01uF  [SM-7351-CAP-0402]
C45  0.01uF  [SM-7351-CAP-0402]
C46  0.01uF  [SM-7351-CAP-0402]
C47  0.01uF  [SM-7351-CAP-0402]
C48  0.01uF  [SM-7351-CAP-0402]
C50  0.01uF  [SM-7351-CAP-0402]
C56  0.1uF  [SM-7351-CAP-0402]
C60  0.01uF  [SM-7351-CAP-0402]
C62  22uF  [SM-7351-CAP-0805]
C63  0.01uF  [SM-7351-CAP-0402]
C67  0.01uF  [SM-7351-CAP-0402]
C70  0.01uF  [SM-7351-CAP-0402]
C71  0.01uF  [SM-7351-CAP-0402]
C72  0.1uF  [SM-7351-CAP-0402]
C73  0.01uF  [SM-7351-CAP-0402]
C74  0.1uF  [SM-7351-CAP-0402]
C77  0.1uF  [SM-7351-CAP-0402]
C78  0.1uF  [SM-7351-CAP-0402]
C80  0.01uF  [SM-7351-CAP-0402]
C81  0.01uF  [SM-7351-CAP-0402]
C82  0.01uF  [SM-7351-CAP-0402]
C83  0.01uF  [SM-7351-CAP-0402]
C86  0.01uF  [SM-7351-CAP-0402]
C87  0.01uF  [SM-7351-CAP-0402]
C89  0.01uF  [SM-7351-CAP-0402]
C90  22uF  [SM-7351-CAP-0805]
C91  0.01uF  [SM-7351-CAP-0402]
C93  0.01uF  [SM-7351-CAP-0402]
C98  0.01uF  [SM-7351-CAP-0402]
C102  0.01uF  [SM-7351-CAP-0402]
C103  0.01uF  [SM-7351-CAP-0402]
C104  0.1uF  [SM-7351-CAP-0402]
C105  0.01uF  [SM-7351-CAP-0402]
C107  0.1uF  [SM-7351-CAP-0402]
C109  0.1uF  [SM-7351-CAP-0402]
C111  0.01uF  [SM-7351-CAP-0402]
C112  0.01uF  [SM-7351-CAP-0402]
C113  0.01uF  [SM-7351-CAP-0402]
C114  0.01uF  [SM-7351-CAP-0402]
C117  0.01uF  [SM-7351-CAP-0402]
C122  0.01uF  [SM-7351-CAP-0402]
C126  0.01uF  [SM-7351-CAP-0402]
C129  22uF  [SM-7351-CAP-0805]
C132  0.01uF  [SM-7351-CAP-0402]
C135  0.01uF  [SM-7351-CAP-0402]
C139  0.01uF  [SM-7351-CAP-0402]
C141  0.01uF  [SM-7351-CAP-0402]
C144  0.01uF  [SM-7351-CAP-0402]
C145  0.01uF  [SM-7351-CAP-0402]
C146  0.1uF  [SM-7351-CAP-0402]
C147  0.1uF  [SM-7351-CAP-0402]
C148  0.01uF  [SM-7351-CAP-0402]
C162  0.1uF  [SM-7351-CAP-0402]
C166  0.01uF  [SM-7351-CAP-0402]
C167  0.01uF  [SM-7351-CAP-0402]
C168  0.01uF  [SM-7351-CAP-0402]
C169  0.01uF  [SM-7351-CAP-0402]
C173  0.01uF  [SM-7351-CAP-0402]
C174  0.01uF  [SM-7351-CAP-0402]
C175  0.01uF  [SM-7351-CAP-0402]
C179  22uF  [SM-7351-CAP-0805]
C183  0.01uF  [SM-7351-CAP-0402]
C185  0.01uF  [SM-7351-CAP-0402]
C187  0.01uF  [SM-7351-CAP-0402]
C190  0.01uF  [SM-7351-CAP-0402]
C191  0.01uF  [SM-7351-CAP-0402]
C192  0.1uF  [SM-7351-CAP-0402]
C193  0.01uF  [SM-7351-CAP-0402]
C195  0.1uF  [SM-7351-CAP-0402]
C288  0.01uF  [SM-7351-CAP-0402]
C307  0.001uF  [SM-7351-CAP-0402]
C315  10uF  [SM-7351-CAP-0805]
C318  10uF  [SM-7351-CAP-0805]
C319  10uF  [SM-7351-CAP-0805]
C321  0.1uF  [SM-7351-CAP-0402]
R34  0  [SM-7351-RES-0402]
R35  10K  [SM-7351-RES-0402]
R36  100K  [SM-7351-RES-0402]
R39  10K  [SM-7351-RES-0402]
R41  10K  [SM-7351-RES-0402]
R43  10  [SM-7351-RES-0402]
R53  47  [SM-7351-RES-0402]
R54  49.9  [SM-7351-RES-0402]
R55  49.9  [SM-7351-RES-0402]
R56  47  [SM-7351-RES-0402]
R62  240  [sm-7351-res-0402]
R63  47  [SM-7351-RES-0402]
R65  47  [SM-7351-RES-0402]
R66  47  [SM-7351-RES-0402]
R67  47  [SM-7351-RES-0402]
R71  47  [SM-7351-RES-0402]
R73  47  [SM-7351-RES-0402]
R78  47  [SM-7351-RES-0402]
R81  47  [SM-7351-RES-0402]
R88  47  [SM-7351-RES-0402]
R89  47  [SM-7351-RES-0402]
R90  47  [SM-7351-RES-0402]
R94  240  [sm-7351-res-0402]
R110  240  [sm-7351-res-0402]
R128  0  [SM-7351-RES-0402]
R129  10K  [SM-7351-RES-0402]
R133  240  [sm-7351-res-0402]
R141  1K  [SM-7351-RES-0402]
R300  47  [SM-7351-RES-0402]
R301  47  [SM-7351-RES-0402]
R302  47  [SM-7351-RES-0402]
R303  47  [SM-7351-RES-0402]
R307  0.05ohm1% Sense  [SM_RES_LVK12]
R314  47  [SM-7351-RES-0402]
R315  47  [SM-7351-RES-0402]
R316  47  [SM-7351-RES-0402]
R319  47  [SM-7351-RES-0402]
R320  47  [SM-7351-RES-0402]
R321  47  [SM-7351-RES-0402]
R322  47  [SM-7351-RES-0402]
R323  47  [SM-7351-RES-0402]
R342  49.9  [SM-7351-RES-0402]
R492  2.2K, 1/8W  [SM-7351-RES-0402]
R493  2.2K, 1/8W  [SM-7351-RES-0402]
U4  TPS51200  [drcpso_10pin]
U55  MT41K512M8RH  [bga11x9-78]
U57  MT41K512M8RH  [bga11x9-78]
U58  MT41K512M8RH  [bga11x9-78]
U60  MT41K512M8RH  [bga11x9-78]
sheet Pg07: Ethernet #1
C262  0.1uF  [SM-7351-CAP-0402]
C263  10uF  [SM-7351-CAP-0805]
C270  0.1uF  [SM-7351-CAP-0402]
C272  10uF  [SM-7351-CAP-0805]
C275  22pF  [SM-7351-CAP-0402]
C276  22pF  [SM-7351-CAP-0402]
C277  10uF  [SM-7351-CAP-0805]
C392  10uF  [SM-7351-CAP-0805]
C393  0.1uF  [SM-7351-CAP-0402]
C394  47uF  [SM-7351-CAP-1206]
C397  0.1uF  [SM-7351-CAP-0402]
C398  10uF  [SM-7351-CAP-0805]
C402  0.1uF  [SM-7351-CAP-0402]
C415  47uF  [SM-7351-CAP-1206]
C420  0.1uF  [SM-7351-CAP-0402]
C421  0.01uF  [SM-7351-CAP-0402]
C425  10uF  [SM-7351-CAP-0805]
C426  0.01uF  [SM-7351-CAP-0402]
C432  0.1uF  [SM-7351-CAP-0402]
D7  MMSD103T1  [sod-123]
FB10  600mAFB10ohm  [HF70ACB201209]
FB21  600mAFB10ohm  [HF70ACB201209]
FB22  600mAFB10ohm  [HF70ACB201209]
FB25  600mAFB10ohm  [HF70ACB201209]
J18  RJ-45 Gigabit  [cnrj45-1x1wled-598m]
J38  HEADER 2  [header_2x1]
Q6  FDT434P  [SOT223-4]
R154  22  [SM-7351-RES-0402]
R156  22  [SM-7351-RES-0402]
R157  22  [SM-7351-RES-0402]
R205  1K  [SM-7351-RES-0402]
R206  1K  [SM-7351-RES-0402]
R209  22  [SM-7351-RES-0402]
R212  22  [SM-7351-RES-0402]
R215  22  [SM-7351-RES-0402]
R217  22  [SM-7351-RES-0402]
R219  22  [SM-7351-RES-0402]
R223  22  [SM-7351-RES-0402]
R226  0  [SM-7351-RES-0402]
R230  0  [SM-7351-RES-0402]
R231  12.1K, 1%  [SM-7351-RES-0402]
R237  4.7K  [SM-7351-RES-0402]
R239  100K  [SM-7351-RES-0402]
R361  22  [SM-7351-RES-0402]
R362  22  [SM-7351-RES-0402]
R363  22  [SM-7351-RES-0402]
R423  220  [SM-7351-RES-0402]
R424  10K  [SM-7351-RES-0402]
R425  10K  [SM-7351-RES-0402]
R427  0  [SM-7351-RES-0603]
R429  1K  [SM-7351-RES-0402]
R430  10K  [SM-7351-RES-0402]
R431  1K  [SM-7351-RES-0402]
R432  10K  [SM-7351-RES-0402]
R433  1K  [SM-7351-RES-0402]
R434  10K  [SM-7351-RES-0402]
R437  1K  [SM-7351-RES-0402]
R438  10K  [SM-7351-RES-0402]
R440  1K  [SM-7351-RES-0402]
R441  10K  [SM-7351-RES-0402]
R444  10K  [SM-7351-RES-0402]
R445  1K  [SM-7351-RES-0402]
R448  10K  [SM-7351-RES-0402]
R451  1.5K  [SM-7351-RES-0402]
R467  220  [SM-7351-RES-0402]
TP25  TP1mm  [tp_smd1mmcircle]
U41  KSZ9031RN  [qfn7x7-48]
U75  SN74LVC1G07  [SC70-5-43M]
Y6  25MHz  [SM_OSC_ABM3]
sheet Pg08: SDMMC0 Interface
U59  AM4378BZDN  [AM437X_ZDN]  (sections -1,-10,-11,-12,-13,-14,-15,-16,-17,-18,-19,-2,-20,-21,-22,-23,-24,-25,-3,-4,-5,-6,-7,-8,-9)
sheet Pg14: Camera #0
A2  OV2659_Module  [DNP]
C12  0.01uF  [SM-7351-CAP-0402]
C33  0.01uF  [SM-7351-CAP-0402]
C34  1uF  [SM-7351-CAP-0402]
C40  0.01uF  [SM-7351-CAP-0402]
C68  0.01uF  [SM-7351-CAP-0402]
C290  0.01uF  [SM-7351-CAP-0402]
C293  0.01uF  [SM-7351-CAP-0402]
C313  0.01uF  [SM-7351-CAP-0402]
C314  0.01uF  [SM-7351-CAP-0402]
C325  2.2uF  [SM-7351-CAP-0603]
C326  15pF  [SM-7351-CAP-0402]
C329  0.1uF  [SM-7351-CAP-0402]
C331  2.2uF  [SM-7351-CAP-0603]
C469  0.01uF  [SM-7351-CAP-0402]
C470  10uF  [SM-7351-CAP-0805]
C471  0.01uF  [SM-7351-CAP-0402]
C472  10uF  [SM-7351-CAP-0805]
J39  FH26-25S-0.3SHW(05)  [CNFH26-25S]
R51  0  [SM-7351-RES-0402]
R52  10K  [SM-7351-RES-0402]
R60  10K  [SM-7351-RES-0402]
R100  0  [SM-7351-RES-0402]
R101  0  [SM-7351-RES-0402]
R103  0  [SM-7351-RES-0402]
R105  0  [SM-7351-RES-0402]
R288  10K  [SM-7351-RES-0402]
R306  0  [SM-7351-RES-0603]
R310  30.1K  [SM-7351-RES-0402]
R312  39K  [SM-7351-RES-0402]
R318  0  [SM-7351-RES-0402]
R329  0  [SM-7351-RES-0402]
R334  0  [SM-7351-RES-0402]
R336  0  [SM-7351-RES-0402]
R339  0  [SM-7351-RES-0402]
R340  0  [SM-7351-RES-0402]
R345  0  [SM-7351-RES-0402]
R348  0  [SM-7351-RES-0402]
R552  4.7K  [SM-7351-RES-0402]
R553  4.7K  [SM-7351-RES-0402]
R555  0  [SM-7351-RES-0402]
R556  10K  [SM-7351-RES-0402]
R557  0  [SM-7351-RES-0402]
R558  10K  [SM-7351-RES-0402]
TP18  TP1mm  [tp_smd1mmcircle]
TP19  TP1mm  [tp_smd1mmcircle]
U8  SN74AVC4T245  [U_16_PW]
U15  SN74AVC8T245  [TSSOP8x4-24-47m]
U47  TXS0102  [dct8]
U50  SN74AVC1T45  [smdsc70-6]
U54  TPS79301  [U_6_DBV]
sheet Pg17: USB Port #0
C198  0.01uF  [SM-7351-CAP-0402]
C199  4.7uF  [SM-7351-CAP-0603]
C344  150uF  [SM-7351-CAP-2917]
FB17  150OHM800mA  [sm-7351-ind-0805]
J11  USB_MicroAB  [ZX62-AB-5PA]
J12  HEADER 2  [header_2x1]
L1  ACM2012  [ACM2012H]
Q2  BSS138  [SOT23-3]
R112  1K  [SM-7351-RES-0402]
R124  10K  [SM-7351-RES-0402]
R126  10K  [SM-7351-RES-0402]
R132  100K  [SM-7351-RES-0402]
R146  10K  [SM-7351-RES-0402]
R148  120K  [SM-7351-RES-0402]
R151  0  [SM-7351-RES-0402]
R350  0  [SM-7351-RES-0402]
TP12  TP  [TH_TP_5002]
U21  TPS2051BD  [U_8_D]
U61  TPD4S012  [U_6_DRY]
sheet Pg19: Wireless COM8
C246  0.01uF  [SM-7351-CAP-0402]
C247  0.01uF  [SM-7351-CAP-0402]
C254  0.01uF  [SM-7351-CAP-0402]
C256  0.01uF  [SM-7351-CAP-0402]
C413  1uF  [SM-7351-CAP-0402]
C419  2.2uF  [SM-7351-CAP-0805]
C422  15pF  [SM-7351-CAP-0402]
C433  0.01uF  [SM-7351-CAP-0402]
C436  0.01uF  [SM-7351-CAP-0402]
J20  MEC6_100pin  [MEC6-150-02-S-D-RA1]
R189  0  [SM-7351-RES-0402]
R195  0  [SM-7351-RES-0402]
R196  0  [SM-7351-RES-0402]
R241  0  [SM-7351-RES-0402]
R242  10K  [SM-7351-RES-0402]
R243  10K  [SM-7351-RES-0402]
R244  10K  [SM-7351-RES-0402]
R245  10K  [SM-7351-RES-0402]
R246  10K  [SM-7351-RES-0402]
R247  10K  [SM-7351-RES-0402]
R248  0  [SM-7351-RES-0402]
R249  0  [SM-7351-RES-0402]
R250  0  [SM-7351-RES-0402]
R251  0  [SM-7351-RES-0402]
R252  0  [SM-7351-RES-0402]
R253  0  [SM-7351-RES-0402]
R254  0  [SM-7351-RES-0402]
R255  0  [SM-7351-RES-0402]
R256  0  [SM-7351-RES-0402]
R257  0  [SM-7351-RES-0402]
R258  0  [SM-7351-RES-0402]
R436  0  [SM-7351-RES-0402]
R439  30.1K  [SM-7351-RES-0402]
R446  57.6K  [SM-7351-RES-0402]
R452  0  [SM-7351-RES-0402]
R453  0  [SM-7351-RES-0402]
R454  0  [SM-7351-RES-0402]
R455  0  [SM-7351-RES-0402]
R456  0  [SM-7351-RES-0402]
R457  0  [SM-7351-RES-0402]
R489  0  [SM-7351-RES-0402]
R490  0  [SM-7351-RES-0402]
TP5  TP1mm  [tp_smd1mmcircle]
TP6  TP1mm  [tp_smd1mmcircle]
TP7  TP1mm  [tp_smd1mmcircle]
TP8  TP1mm  [tp_smd1mmcircle]
U33  SN74AVC4T245  [U_16_PW]
U34  SN74AVC1T45  [smdsc70-6]
U71  TPS79601  [sot223_6pin]

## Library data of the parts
M3-M6 = 2M_Screw_4-40_5_8
M7-M10 = 2M_Screw_4-40_1_4
M11-M14 = 2M_Standoff4-40x1_4x5_8Alum
M15-M18 = 2M_RubberFeet_screwno4
PCB1 = 3K_AM437xGPEVMBarePCB
C8 C27 C28 C57 C197 C208-C210 C214 C263 C272 C277 C315 C318 C319 C333 C347 C351-C353 C392 C398 C425 C470 C472 = 1C_10uFCapacitor16V10%0805
C12 C33 C40 C43-C48 C50 C60 C63 C67 C68 C70 C71 C73 C80-C83 C86-C89 C91 C93 C98 C102 C103 C105 C111-C114 C117-C124 C126 C128 C130-C145 C148-C154 C156-C161 C163 C165-C178 C183 C185 C187-C191 C193 C196 C198 C202-C207 C246 C247 C254 C256 C288 C290 C292 C293 C313 C314 C345 C346 C350 C354-C359 C421 C426 C433 C436 C469 C471 C473 = 1C_0.01uFCapacitor16V10%0402
C34 C110 C164 C181 C182 C413 = 1C_1uFCapacitor10V10%0402
C125 C419 = 1C_2.2uF16V10%SMD0805
C194 C201 = 1C_10uFCapacitor6.3V20%0603
FB2-FB9 FB16 FB17 FB19 = 1L_FerBead_180ohm200mA
J12 J28 J31 J38 = 2H_Header_2x1
J42 = 2H_Header_4x1
R68 R155 = 1R_0.1ohm0.33W1%Sense0805
R34 R51 R74 R100-R103 R105 R111 R122 R128 R151 R189 R195 R196 R226 R230 R241 R248-R258 R318 R329 R334 R336 R339 R340 R345 R348 R350 R436 R452-R457 R489 R490 R555 R557 R638 R639 = 1R_ZeroOhmResistor1_16W0402
R145 R159 R306 R333 R427 = 1R_ZeroOhmResistor1_16W0603
R305 R307 R317 R328 = 1R_0.05ohm0.5W1%Sense1206
R35 R39 R41 R52 R60 R124 R126 R129 R146 R242-R247 R288 R424 R425 R430 R432 R434 R438 R441 R444 R448 R556 R558 R640 = 1R_10KOhmResistor1_16W0402
SCKT1 = AM437X_ZDN_Processor_Socket
TP5-TP8 TP18 TP19 TP22 TP25 = 2H_Testpoint_SMD1mmCircle
C15 C23 C24 C36 C39 C41 C56 C72 C74 C77 C78 C104 C107 C109 C146 C147 C162 C192 C195 C262 C270 C321 C329 C393 C402 C420 = 1C_0.1uFCapacitor16V10%0402
C20 C307 = 1C_0.001uFCapacitor50V5%0402
C21 = 1C_10pFCapacitor50V1%smd0402
C62 C90 C129 C179 = 1C_22uFCapacitor16V10%0805
R36 R132 R239 = 1R_100KOhmResistor1_16W0402
R43 = 1R_10ohm1_16W5%smd0402
R53 R56 R63 R65-R67 R71 R73 R78 R81 R88-R90 R300-R303 R314-R316 R319-R323 = 47ohm1_16W1%smd0402
R54 R55 R342 = 1R_49.9OhmResistor1_16W0402
R62 R94 R110 R133 = 1R_240OhmResistor1_16W0402
R112 R141 R205 R206 R429 R431 R433 R437 R440 R445 = 1R_1KOhmResistor1_16W0402
R492 R493 = 1R_2.2KohmResistor1_8W1%0402
U4 = TPS51200
U55 U57 U58 U60 = 1A_MT41K512M8RH
C275 C276 = 1C_22pFCapacitor50V10%SMD0402
C394 C415 = 1C_47uFCapacitor16V20%1206
C397 C432 = 1C_0.1uFCapacitor50V10%0402
D7 = Diode200mA250V
FB10 FB21 FB22 FB25 = 1L_FerriteBead_600mA10ohm
J18 = 2J_ConnectorRJ45_Gigabit
Q6 = 1Q_MOSFET_PChan_FDT434P
R154 R156 R157 R209 R212 R215 R217 R219 R223 R361-R363 = 1R_22OhmResistor1_16W1%0402
R231 = 1R_12.1KohmResistor1_16W1%0402
R237 R552 R553 = 1R_4.7KOhmResistor1_16W0402
R423 R467 = 1R_220ohm1_10W1%smd0402
R451 = 1R_1.5KohmResistor1_16W5%0402
U41 = 1A_KSZ9031RNX
U75 = 1A_SN74LVC1G07
Y6 = 1Y_Crystal25MHzABM3
U59 = AM4378_ZDN_GPEVM
A2 = 4P_CameraModuleOV2659_2MpDI
C325 C331 = 1C_2.2uFCapacitor6.3V10%smd0603
C326 C422 = 1C_15pFCapacitor50V10%smd0402
J39 = 2C_Conn_FFC_0.3mm_25pos
R310 R439 = 1R_30.1Kohm1_16W1%smd0402
R312 = 1R_39Kohm1_16W5%smd0402
U8 U33 = 1A_SN74AVC4T245
U15 = 1A_SN74AVC8T245
U47 = 1A_TXS0102
U34 U50 = 1A_SN74AVC1T45
U54 = 1A_TPS79301
C199 = 1C_4.7uFCapacitor16V10%0603
C344 = 1C_150uFCapacitor10V10%2917
J11 = 2C_MicroUSBAB
L1 = 1M_ACM2012
Q2 = 1Q_MOSFET_NChan_BSS138
R148 = 1R_120Kohm1_16W1%SMD0402
TP12 = 2H_TestPointThroughHole
U21 = 1A_TPS2051BD
U61 = 1A_TPD4S012
J20 = 2C_Conn_SamtecMEC6_150
R446 = 1R_57.6Kohm1_10W1%smd0402
U71 = 1A_TPS79601

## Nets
AGNDCAM: C471.2 C472.2 J39.24 R555.2(P2)
DGND: C8.2 C12.2 C15.2 C20.2 C21.2 C23.2 C24.2 C27.2 C28.2 C33.2 C34.2 C36.2 C39.2 C40.2 C41.2 C43.2 C44.2 C45.2 C46.2 C47.2 C48.2 C50.2 C56.2 C57.2 C60.2 C62.2 C63.2 C67.2 C68.2 C70.2 C71.2 C72.2 C73.2 C77.2 C78.2 C80.2 C81.2 C82.2 C83.2 C86.2 C87.2 C88.2 C89.2 C90.2 C91.2 C93.2 C98.2 C102.2 C103.2 C104.2 C105.2 C109.2 C110.2 C111.2 C112.2 C113.2 C114.2 C117.2 C118.2 C119.2 C120.2 C121.2 C122.2 C125.2 C126.2 C128.2 C129.2 C130.2 C131.2 C132.2 C133.2 C134.2 C135.2 C136.2 C137.2 C138.2 C139.2 C140.2 C141.2 C142.2 C143.2 C144.2 C145.2 C147.2 C148.2 C149.2 C150.2 C151.2 C152.2 C153.2 C154.2 C156.2 C157.2 C158.2 C159.2 C160.2 C161.2 C162.2 C163.2 C164.2 C165.2 C166.2 C167.2 C168.2 C169.2 C170.2 C171.2 C172.2 C173.2 C174.2 C175.2 C176.2 C177.2 C178.2 C179.2 C181.2 C182.2 C183.2 C185.2 C187.2 C188.2 C189.2 C190.2 C191.2 C192.2 C193.2 C194.2 C196.2 C197.2 C198.2 C199.2 C201.2 C202.2 C203.2 C204.2 C205.2 C206.2 C207.2 C208.2 C209.2 C210.2 C214.2 C246.2 C247.2 C254.2 C256.2 C262.2 C263.2 C270.2 C272.2 C275.1 C276.1 C277.2 C290.2 C292.2 C293.2 C307.2 C313.2 C314.2 C315.2 C318.2 C319.2 C325.2 C329.2 C331.2 C333.2 C344.2(NEG) C345.2 C346.2 C347.2 C350.2 C351.2 C352.2 C353.2 C354.2 C355.2 C356.2 C357.2 C358.2 C359.2 C392.2 C393.2 C394.2 C397.1 C398.2 C402.2 C413.2 C415.2 C419.2 C420.2 C421.2 C425.2 C426.2 C432.1 C433.2 C436.2 C469.2 C470.2 C473.2 FB17.1 J11.5(GND) J18.1 J20.2 J20.3 J20.6 J20.9 J20.18 J20.19 J20.22 J20.35 J20.37 J20.39 J20.42 J20.47 J20.60 J20.63 J20.64 J20.77 J20.83 J20.87 J20.92 J20.95 J20.97 J38.2 J39.11 J39.MNT1 J39.MNT2 J42.1 Q2.S(SOURCE) R35.1(P1) R39.1(P1) R60.1(P1) R62.1(P1) R94.1(P1) R102.1(P1) R110.1(P1) R111.1(P1) R129.1(P1) R132.1(P1) R133.1(P1) R145.2(P2) R146.2(P2) R148.1(P1) R189.1(P1) R195.1(P1) R205.1(P1) R206.1(P1) R231.2 R310.1(P1) R342.1(P1) R429.1(P1) R431.1(P1) R433.1(P1) R437.1(P1) R439.1(P1) R440.1(P1) R445.1(P1) R493.2 R555.1(P1) R557.1(P1) R558.1(P1) R640.1(P1) U4.4(PGND) U4.8(GND) U4.11(PWRPD) U8.3(2DIR) U8.8(GND) U8.9(GND) U15.2(DIR) U15.11(GND) U15.12(GND) U15.13(GND) U21.1(GND) U33.8(GND) U33.9(GND) U33.14(2~{OE}) U33.15(1~{OE}) U34.2(GND) U41.13(VSS_PS) U41.29(VSS) U41.49(P_GND) U47.2(GND) U50.2(GND) U50.5(DIR) U54.2(GND) U55.A1(VSS) U55.A8(VSS) U55.B1(VSS) U55.B2(VSSQ) U55.B8(VSSQ) U55.C9(VSSQ) U55.D1(VSSQ) U55.D8(VSS) U55.D9(VSSQ) U55.F2(VSS) U55.F8(VSS) U55.J1(VSS) U55.J9(VSS) U55.L1(VSS) U55.L9(VSS) U55.N1(VSS) U55.N9(VSS) U57.A1(VSS) U57.A8(VSS) U57.B1(VSS) U57.B2(VSSQ) U57.B8(VSSQ) U57.C9(VSSQ) U57.D1(VSSQ) U57.D8(VSS) U57.D9(VSSQ) U57.F2(VSS) U57.F8(VSS) U57.J1(VSS) U57.J9(VSS) U57.L1(VSS) U57.L9(VSS) U57.N1(VSS) U57.N9(VSS) U58.A1(VSS) U58.A8(VSS) U58.B1(VSS) U58.B2(VSSQ) U58.B8(VSSQ) U58.C9(VSSQ) U58.D1(VSSQ) U58.D8(VSS) U58.D9(VSSQ) U58.F2(VSS) U58.F8(VSS) U58.J1(VSS) U58.J9(VSS) U58.L1(VSS) U58.L9(VSS) U58.N1(VSS) U58.N9(VSS) U59.A1(GND) U59.A25(GND) U59.AE1(GND) U59.AE25(GND) U59.H15(GND) U59.H18(GND) U59.J9(GND) U59.J12(GND) U59.J15(GND) U59.J17(GND) U59.K9(GND) U59.K11(GND) U59.K12(GND) U59.K14(GND) U59.K15(GND) U59.L8(GND) U59.L9(GND) U59.L11(GND) U59.L15(GND) U59.L17(GND) U59.L18(GND) U59.M10(GND) U59.M11(GND) U59.M13(GND) U59.M15(GND) U59.M16(GND) U59.N10(GND) U59.N11(GND) U59.N12(GND) U59.N13(GND) U59.N14(GND) U59.N15(GND) U59.P8(GND) U59.P9(GND) U59.P10(GND) U59.P11(GND) U59.P12(GND) U59.P13(GND) U59.P14(GND) U59.P15(GND) U59.R12(GND) U59.R15(GND) U59.R17(GND) U59.R18(GND) U59.T12(GND) U59.T15(GND) U59.T17(GND) U59.U8(GND) U59.U9(GND) U59.U10(GND) U59.U11(GND) U59.U12(GND) U59.U13(GND) U59.U14(GND) U59.U16(GND) U59.U17(GND) U59.U18(GND) U59.U19(GND) U59.V9(GND) U59.V10(GND) U59.V11(GND) U59.V12(GND) U59.V13(GND) U59.V14(GND) U59.V18(GND) U59.W23(VSSA_USB) U60.A1(VSS) U60.A8(VSS) U60.B1(VSS) U60.B2(VSSQ) U60.B8(VSSQ) U60.C9(VSSQ) U60.D1(VSSQ) U60.D8(VSS) U60.D9(VSSQ) U60.F2(VSS) U60.F8(VSS) U60.J1(VSS) U60.J9(VSS) U60.L1(VSS) U60.L9(VSS) U60.N1(VSS) U60.N9(VSS) U61.4(GND) U71.3(GND) U71.6(GND) U75.3(GND) ; also on sheet 1 2 4 5 6 7 8 9 10 11 19 20 21 22 23 24 25 26 27
GND_ETH1: C397.2 C432.2 J18.SHLD1 J18.SHLD2
GNDA_ADC: C123.2 C124.2 R102.2(P2) U59.AC15(VSSA_ADC) ; also on sheet 3
GNDUSB0: FB17.2 J11.S1 J11.S2 J11.S3 J11.S4
V1_0BAT: R333.2(P2) ; also on sheet 23
V1_8BAT: R74.1(P1) ; also on sheet 23
V1_8D: C12.1 C40.1 C254.1 C256.1 C293.1 C313.1 C433.1 C469.1 C470.1 J20.8 J20.62 J39.15 R68.1(I1) R196.1(P1) R242.2(P2) R243.2(P2) R244.2(P2) R245.2(P2) R246.2(P2) R247.2(P2) R318.2(P2) R436.2(P2) R552.2(P2) R553.2(P2) R556.2(P2) U8.16(VCCB) U15.23(VCCB) U15.24(VCCB) U33.1(VCCA) U34.1(VCCA) U47.3(VCCA) U50.6(VCCB) ; also on sheet 2 3 4 23 25
V1_8D_AM437X: C119.1 C120.1 C121.1 C130.1 C176.1 C177.1 C178.1 C189.1 C196.1 C197.1 C345.1 C346.1 C347.1 FB2.2 FB3.2 FB4.1 FB5.1 FB6.1 FB7.1 FB8.1 FB9.1 FB16.2 FB19.1 R68.2(I2) U59.AD8(VDDS_TPM) U59.C23(VDDS_OSC) U59.F20(VDDS) U59.G6(VDDS) U59.G11(VDDSHV9) U59.H8(VDDSHV11) U59.H9(VDDSHV11) U59.H11(VDDSHV9) U59.H12(VDDS) U59.P19(VDDS) U59.U21(VDDA1P8V_USB1) U59.W15(VDDS) U59.Y19(VDDS)
V2_8A: C471.1 C472.1 J39.22 R306.1(P1)
V2_8A_EN: R318.1(P1) U54.3(EN)
V2_8A_FB: C326.2 R310.2(P2) R312.1(P1) U54.5(FB)
V2_8A_OUT: C325.1 C326.1 R306.2(P2) R312.2(P2) U54.6(OUT)
V3_3D: C8.1 C33.1 C68.1 C246.1 C247.1 C290.1 C314.1 FB10.1 J42.3 R36.2(P2) R52.2(P2) R124.1(P1) R126.2(P2) R155.1(I1) R288.2(P2) R423.2 R427.2(P2) R467.2 U4.10(VIN) U8.1(VCCA) U8.2(1DIR) U15.1(VCCA) U33.16(VCCB) U34.6(VCCB) U47.7(VCCB) U50.1(VCCA) ; also on sheet 1 2 4 5 6 7 8 9 10 11 20 21 22 23 24 25 27
V3_3D_AM437X: C133.1 C158.1 C165.1 C170.1 C202.1 C203.1 C204.1 C205.1 C206.1 C207.1 C208.1 C209.1 C210.1 C350.1 C351.1 C352.1 C353.1 C354.1 C355.1 C356.1 C357.1 C358.1 C359.1 R122.2(P2) R155.2(I2) U59.F16(VDDSHV7) U59.F22(VDDSHV5) U59.G10(VDDSHV10) U59.G13(VDDSHV8) U59.G14(VDDSHV8) U59.G16(VDDSHV6) U59.G17(VDDSHV6) U59.H10(VDDSHV10) U59.H17(VDDSHV6) U59.J7(VDDSHV1) U59.J8(VDDSHV1) U59.J18(VDDSHV3) U59.K17(VDDSHV3) U59.K18(VDDSHV3) U59.N18(VDDSHV3) U59.N19(VDDSHV3) U59.P18(VDDSHV3) U59.V16(VDDSHV2) U59.V17(VDDSHV2) U59.W16(VDDSHV2) U59.W18(VDDSHV3)
V5_0D: U21.2(IN) U21.3(IN) ; also on sheet 5 9 23
VBAT: C331.1 C413.1 U54.1(IN) U71.2(IN) ; also on sheet 1 3 4 5 11 19 21 23 27
VBUS0_OTG_CAP: C344.1(POS) J12.2
VDD_CORE: C128.1 C137.1 C138.1 C140.1 C142.1 C150.1 C153.1 C156.1 C333.1 J31.1 R328.2(I2) U59.AD9(VDD_TPM) U59.J10(VDD_CORE) U59.J11(VDD_CORE) U59.L12(VDD_CORE) U59.L14(VDD_CORE) U59.M9(VDD_CORE) U59.M12(VDD_CORE) U59.M14(VDD_CORE) U59.N9(VDD_CORE) U59.N16(VDD_CORE) U59.N17(VDD_CORE) U59.P16(VDD_CORE) U59.P17(VDD_CORE) U59.R9(VDD_CORE) U59.R11(VDD_CORE) U59.R14(VDD_CORE) U59.T9(VDD_CORE) U59.T11(VDD_CORE) U59.T14(VDD_CORE) U59.T18(VDD_CORE) U59.T19(VDD_CORE) U59.U15(VDD_CORE) U59.V15(VDD_CORE) U59.W12(VDD_CORE) U59.W13(VDD_CORE)
VDD_MPU: C57.1 C88.1 C154.1 C157.1 C160.1 C163.1 J28.1 R317.2(I2) U59.H13(VDD_MPU) U59.H14(VDD_MPU) U59.H16(VDD_MPU) U59.J13(VDD_MPU) U59.J14(VDD_MPU) U59.J16(VDD_MPU) U59.K19(VDD_MPU) U59.K20(VDD_MPU) U59.L19(VDD_MPU) U59.L20(VDD_MPU) U59.M17(VDD_MPU) U59.M18(VDD_MPU)
VDDA1_8_USB0: C125.1 C131.1 FB4.2 U59.W21(VDDA1P8V_USB0)
VDDA1P8_PMLDO: R159.1(P1) U59.D6(VDDA1P8_PMLDO)
VDDA3_3_USB: C143.1 R122.1(P1) U59.U20(VDDA_3P3V_USB1) U59.W20(VDDA_3P3V_USB0)
VDDA3P3_PMLDO: R145.1(P1) U59.F8(VDDA3P3_PMLDO)
VDDA_ADC: C123.1 FB2.1 U59.AB12(VDDA_TS_ADC) ; also on sheet 3
VDDA_MC_ADC: C124.1 FB3.1 U59.Y16(VDDA_MC_ADC) ; also on sheet 3
VDDR_VREF: C15.1 C39.1 C72.1 C74.2 C77.1 C104.1 C107.2 C109.1 C146.2 C147.1 C162.1 C192.1 C195.2 U4.6(REFOUT) U55.E1(VREFDQ) U55.J8(VREFCA) U57.E1(VREFDQ) U57.J8(VREFCA) U58.E1(VREFDQ) U58.J8(VREFCA) U60.E1(VREFDQ) U60.J8(VREFCA)
VDDR_VTT: C24.1 C28.1 C36.1 C41.1 C56.1 C78.1 C318.1 C319.1 R43.2(P2) R53.1(P1) R56.1(P1) R63.1(P1) R65.1(P1) R66.1(P1) R67.1(P1) R71.1(P1) R73.1(P1) R78.1(P1) R81.1(P1) R88.1(P1) R89.1(P1) R90.1(P1) R300.1(P1) R301.1(P1) R302.1(P1) R303.1(P1) R314.1(P1) R315.1(P1) R316.1(P1) R319.1(P1) R320.1(P1) R321.1(P1) R322.1(P1) R323.1(P1) U4.3(VO)
VDDS_CTM: FB16.1 U59.AD12(VDDS_CTM)
VDDS_DDR: C23.1 C27.1 C43.1 C44.1 C45.1 C46.1 C47.1 C48.1 C50.1 C60.1 C62.1 C63.1 C67.1 C70.1 C71.1 C73.1 C74.1 C80.1 C81.1 C82.1 C83.1 C86.1 C87.1 C89.1 C90.1 C91.1 C93.1 C98.1 C102.1 C103.1 C105.1 C107.1 C111.1 C112.1 C113.1 C114.1 C117.1 C122.1 C126.1 C129.1 C132.1 C135.1 C139.1 C144.1 C145.1 C146.1 C148.1 C166.1 C167.1 C168.1 C169.1 C173.1 C174.1 C175.1 C179.1 C183.1 C185.1 C187.1 C190.1 C191.1 C193.1 C195.1 C307.1 C315.1 C321.2 R41.2(P2) R141.2(P2) R307.2(I2) U4.2(VLDOIN) U55.A2(VDD) U55.A9(VDD) U55.B9(VDDQ) U55.C1(VDDQ) U55.D7(VDD) U55.E2(VDDQ) U55.E9(VDDQ) U55.G2(VDD) U55.G8(VDD) U55.K1(VDD) U55.K9(VDD) U55.M1(VDD) U55.M9(VDD) U57.A2(VDD) U57.A9(VDD) U57.B9(VDDQ) U57.C1(VDDQ) U57.D7(VDD) U57.E2(VDDQ) U57.E9(VDDQ) U57.G2(VDD) U57.G8(VDD) U57.K1(VDD) U57.K9(VDD) U57.M1(VDD) U57.M9(VDD) U58.A2(VDD) U58.A9(VDD) U58.B9(VDDQ) U58.C1(VDDQ) U58.D7(VDD) U58.E2(VDDQ) U58.E9(VDDQ) U58.G2(VDD) U58.G8(VDD) U58.K1(VDD) U58.K9(VDD) U58.M1(VDD) U58.M9(VDD) U60.A2(VDD) U60.A9(VDD) U60.B9(VDDQ) U60.C1(VDDQ) U60.D7(VDD) U60.E2(VDDQ) U60.E9(VDDQ) U60.G2(VDD) U60.G8(VDD) U60.K1(VDD) U60.K9(VDD) U60.M1(VDD) U60.M9(VDD)
VDDS_PLL_CORE_LCD: C151.1 FB5.2 U59.N21(VDDS_PLL_CORE_LCD)
VDDS_PLL_DDR: C172.1 FB8.2 U59.G5(VDDS_PLL_DDR)
VDDS_PLL_MPU: C171.1 FB9.2 U59.E17(VDDS_PLL_MPU)
VDDS_RTC: C118.1 R74.2(P2) U59.AD5(VDDS_RTC) ; also on sheet 23 24
VDDS_SRAM_CORE_BG: C194.1 FB7.2 U59.F13(VDDS_SRAM_CORE_BG)
VDDS_SRAM_MPU_BB: C201.1 FB19.2 U59.F14(VDDS_SRAM_MPU_BB)
AM437X_CAM0_DATA0: R336.2(P2) U59.AE18(CAM0_DATA0)
AM437X_CAM0_DATA1: R100.2(P2) U59.AB18(CAM0_DATA1)
AM437X_CAM0_DATA2: R103.2(P2) U59.Y18(CAM0_DATA2)
AM437X_CAM0_DATA3: R101.2(P2) U59.AA18(CAM0_DATA3)
AM437X_CAM0_DATA4: R340.2(P2) U59.AE19(CAM0_DATA4)
AM437X_CAM0_DATA5: R339.2(P2) U59.AD19(CAM0_DATA5)
AM437X_CAM0_DATA6: R348.2(P2) U59.AE20(CAM0_DATA6)
AM437X_CAM0_DATA7: R345.2(P2) U59.AD20(CAM0_DATA7)
AM437X_CAM0_DATA8: TP19.1 U59.AB19(CAM0_DATA8)
AM437X_CAM0_DATA9: TP18.1 U59.AA19(CAM0_DATA9)
AM437X_CAM0_HSYNC: R329.2(P2) U59.AE17(CAM0_HSYNC)
AM437X_CAM0_PCLK: R105.2(P2) U59.AC20(CAM0_PCLK)
AM437X_CAM0_VSYNC: R334.2(P2) U59.AD18(CAM0_VSYNC)
AM437X_COM_BTRST: R489.2(P2) U59.C3(GPMC_A0/GPIO)
AM437X_COM_PPSOUT: R250.1(P1) U59.E7(GPMC_A5/GPIO)
AM437X_COM_TIMESTAMP: R249.1(P1) U59.E8(GPMC_A6/GPIO)
AM437X_COM_WLANIRQ: R248.1(P1) U59.F6(GPMC_A7/GPIO)
AM437X_COM_WLRST: R241.1(P1) U59.D7(GPMC_A4/GPIO)
AM437X_RGMII1_RXCLK: R223.2(P2) U59.D13(GMII1_RXCLK/RGMII1_RCLK)
AM437X_RGMII1_RXCTL: R219.2(P2) U59.A15(GMII1_RXDV/RGMII1_RCTL)
AM437X_RGMII1_RXD0: R217.2(P2) U59.F17(GMII1_RXD0/RGMII1_RD0)
AM437X_RGMII1_RXD1: R215.2(P2) U59.B16(GMII1_RXD1/RGMII1_RD1)
AM437X_RGMII1_RXD2: R212.2(P2) U59.E16(GMII1_RXD2/RGMII1_RD2)
AM437X_RGMII1_RXD3: R209.2(P2) U59.C14(GMII1_RXD3/RGMII1_RD3)
AM437X_RGMII1_TXCLK: R157.2(P2) U59.D14(GMII1_TXCLK/RGMII1_TCLK)
AM437X_RGMII1_TXCTL: R363.2(P2) U59.A13(GMII1_TXEN/RGMII1_TCTL)
AM437X_RGMII1_TXD0: R361.2(P2) U59.B15(GMII1_TXD0/RGMII1_TD0)
AM437X_RGMII1_TXD1: R362.2(P2) U59.A14(GMII1_TXD1/RGMII1_TD1)
AM437X_RGMII1_TXD2: R156.2(P2) U59.C13(GMII1_TXD2/RGMII1_TD2)
AM437X_RGMII1_TXD3: R154.2(P2) U59.C16(GMII1_TXD3/RGMII1_TD3)
AM437X_STATUS_LED5: R638.2(P2) ; also on sheet 19 21
AM437X_USB0_CE: TP12.1 U59.W22(USB0_CE)
AM437X_USB0_DM: L1.2 U59.W24(USB0_DM)
AM437X_USB0_DP: L1.1 U59.W25(USB0_DP)
AM437X_USB0_ID: R350.2(P2) U59.U24(USB0_ID)
AM437X_USB0_VBUS: R112.2(P2) U59.U23(USB0_VBUS)
AM437X_VDDR_VREF: C141.1 C288.2 R492.2 R493.1 U59.T6(DDR_VREF)
AUDIO_MSTRCLK: R51.2(P2) ; also on sheet 2 5 11
CAM0_DATA0: R336.1(P1) U15.3(A1)
CAM0_DATA1: R100.1(P1) U15.4(A2)
CAM0_DATA2: R103.1(P1) U15.5(A3)
CAM0_DATA3: R101.1(P1) U15.6(A4)
CAM0_DATA4: R340.1(P1) U15.7(A5)
CAM0_DATA5: R339.1(P1) U15.8(A6)
CAM0_DATA6: R348.1(P1) U15.9(A7)
CAM0_DATA7: R345.1(P1) U15.10(A8)
CAM0_GIO0: C34.1 R52.1(P1) U8.5(1A2)
CAM0_HSYNC: R329.1(P1) U8.7(2A2)
CAM0_PCLK: R105.1(P1) U50.3(A)
CAM0_SRCCLK: R51.1(P1) U8.4(1A1)
CAM0_VSYNC: R334.1(P1) U8.6(2A1)
CAP_VBB_MPU: C164.1 U59.F19(CAP_VBB_MPU)
CAP_VDD_SRAM_CORE: C181.1 U59.E13(CAP_VDD_SRAM_CORE)
CAP_VDD_SRAM_MPU: C182.1 U59.E14(CAP_VDD_SRAM_MPU)
COM_AUD_CLK: J20.52 R251.2(P2)
COM_AUD_FSYNC: J20.54 R252.2(P2)
COM_AUD_IN: J20.56 R253.2(P2)
COM_AUD_OUT: J20.58 R254.2(P2)
COM_BTRST: J20.89 R489.1(P1)
COM_BTUARTCTS: J20.70 R257.2(P2)
COM_BTUARTDEBUG: J20.76 TP5.1
COM_BTUARTRTS: J20.72 R258.2(P2)
COM_BTUARTRX: J20.68 R256.2(P2)
COM_BTUARTTX: J20.66 R255.2(P2)
COM_GNSS_PPS_OUT: J20.50 R250.2(P2)
COM_GNSS_TIME_STAMP: J20.48 R249.2(P2)
COM_SDIO_CLK: J20.20 R242.1(P1) R457.2(P2)
COM_SDIO_CMD: J20.24 R243.1(P1) R456.2(P2)
COM_SDIO_D0: J20.26 R244.1(P1) R455.2(P2)
COM_SDIO_D1: J20.28 R245.1(P1) R454.2(P2)
COM_SDIO_D2: J20.30 R246.1(P1) R453.2(P2)
COM_SDIO_D3: J20.32 R247.1(P1) R452.2(P2)
COM_SLOW_CLK: J20.1 R490.1(P1)
COM_WL_IRQ: J20.34 R248.2(P2)
COM_WL_RS232_RX: J20.13 TP7.1
COM_WL_RS232_TX: J20.11 TP8.1
COM_WL_RST: J20.4 R241.2(P2)
COM_WL_UART_DBG: J20.15 TP6.1
DDR_A0: R73.2(P2) U55.K3(A0) U57.K3(A0) U58.K3(A0) U59.N1(DDR_A0) U60.K3(A0)
DDR_A1: R66.2(P2) U55.L7(A1) U57.L7(A1) U58.L7(A1) U59.L1(DDR_A1) U60.L7(A1)
DDR_A2: R316.2(P2) U55.L3(A2) U57.L3(A2) U58.L3(A2) U59.L2(DDR_A2) U60.L3(A2)
DDR_A3: R321.2(P2) U55.K2(A3) U57.K2(A3) U58.K2(A3) U59.P2(DDR_A3) U60.K2(A3)
DDR_A4: R301.2(P2) U55.L8(A4) U57.L8(A4) U58.L8(A4) U59.P1(DDR_A4) U60.L8(A4)
DDR_A5: R320.2(P2) U55.L2(A5) U57.L2(A5) U58.L2(A5) U59.R5(DDR_A5) U60.L2(A5)
DDR_A6: R302.2(P2) U55.M8(A6) U57.M8(A6) U58.M8(A6) U59.R4(DDR_A6) U60.M8(A6)
DDR_A7: R78.2(P2) U55.M2(A7) U57.M2(A7) U58.M2(A7) U59.R3(DDR_A7) U60.M2(A7)
DDR_A8: R303.2(P2) U55.N8(A8) U57.N8(A8) U58.N8(A8) U59.R2(DDR_A8) U60.N8(A8)
DDR_A9: R71.2(P2) U55.M3(A9) U57.M3(A9) U58.M3(A9) U59.R1(DDR_A9) U60.M3(A9)
DDR_A10: R53.2(P2) U55.H7(A10/AP) U57.H7(A10/AP) U58.H7(A10/AP) U59.M6(DDR_A10) U60.H7(A10/AP)
DDR_A11: R65.2(P2) U55.M7(A11) U57.M7(A11) U58.M7(A11) U59.T5(DDR_A11) U60.M7(A11)
DDR_A12: R63.2(P2) U55.K7(A12/~{BC}) U57.K7(A12/~{BC}) U58.K7(A12/~{BC}) U59.T4(DDR_A12) U60.K7(A12/~{BC})
DDR_A13: R319.2(P2) U55.N3(A13) U57.N3(A13) U58.N3(A13) U59.N5(DDR_A13) U60.N3(A13)
DDR_A14: R314.2(P2) U55.N7(A14) U57.N7(A14) U58.N7(A14) U59.T3(DDR_A14) U60.N7(A14)
DDR_A15: R67.2(P2) U55.J7(A15) U57.J7(A15) U58.J7(A15) U59.T2(DDR_A15) U60.J7(A15)
DDR_BA0: R322.2(P2) U55.J2(BA0) U57.J2(BA0) U58.J2(BA0) U59.K1(DDR_BA0) U60.J2(BA0)
DDR_BA1: R300.2(P2) U55.K8(BA1) U57.K8(BA1) U58.K8(BA1) U59.K2(DDR_BA1) U60.K8(BA1)
DDR_BA2: R81.2(P2) U55.J3(BA2) U57.J3(BA2) U58.J3(BA2) U59.K3(DDR_BA2) U60.J3(BA2)
DDR_CASN: R90.2(P2) U55.G3(CASn) U57.G3(CASn) U58.G3(CASn) U59.N3(DDR_CASn) U60.G3(CASn)
DDR_CKE: R56.2(P2) R128.1(P1) U55.G9(CKE) U57.G9(CKE) U58.G9(CKE) U60.G9(CKE)
DDR_CKE0: R128.2(P2) R129.2(P2) U59.M3(DDR_CKE0)
DDR_CLK: R55.2(P2) U55.F7(CK) U57.F7(CK) U58.F7(CK) U59.M2(DDR_CK) U60.F7(CK)
DDR_CLKn: R54.2(P2) U55.G7(CKn) U57.G7(CKn) U58.G7(CKn) U59.M1(DDR_CKn) U60.G7(CKn)
DDR_CS0n: R89.2(P2) U55.H2(CSn) U57.H2(CSn) U58.H2(CSn) U59.M5(DDR_CSN0) U60.H2(CSn)
DDR_D0: U59.E3(DDR_D0) U60.B3(DQ0)
DDR_D1: U59.E2(DDR_D1) U60.C7(DQ1)
DDR_D2: U59.E1(DDR_D2) U60.C2(DQ2)
DDR_D3: U59.F3(DDR_D3) U60.C8(DQ3)
DDR_D4: U59.G4(DDR_D4) U60.E3(DQ4)
DDR_D5: U59.G3(DDR_D5) U60.E8(DQ5)
DDR_D6: U59.G2(DDR_D6) U60.D2(DQ6)
DDR_D7: U59.G1(DDR_D7) U60.E7(DQ7)
DDR_D8: U58.B3(DQ0) U59.H1(DDR_D8)
DDR_D9: U58.C7(DQ1) U59.J6(DDR_D9)
DDR_D10: U58.C2(DQ2) U59.J5(DDR_D10)
DDR_D11: U58.C8(DQ3) U59.J4(DDR_D11)
DDR_D12: U58.E3(DQ4) U59.J3(DDR_D12)
DDR_D13: U58.E8(DQ5) U59.K6(DDR_D13)
DDR_D14: U58.D2(DQ6) U59.K5(DDR_D14)
DDR_D15: U58.E7(DQ7) U59.K4(DDR_D15)
DDR_D16: U57.B3(DQ0) U59.V5(DDR_D16)
DDR_D17: U57.C7(DQ1) U59.V4(DDR_D17)
DDR_D18: U57.C2(DQ2) U59.V3(DDR_D18)
DDR_D19: U57.C8(DQ3) U59.V2(DDR_D19)
DDR_D20: U57.E3(DQ4) U59.V1(DDR_D20)
DDR_D21: U57.E8(DQ5) U59.W4(DDR_D21)
DDR_D22: U57.D2(DQ6) U59.W5(DDR_D22)
DDR_D23: U57.E7(DQ7) U59.W6(DDR_D23)
DDR_D24: U55.B3(DQ0) U59.Y2(DDR_D24)
DDR_D25: U55.C7(DQ1) U59.Y3(DDR_D25)
DDR_D26: U55.C2(DQ2) U59.Y4(DDR_D26)
DDR_D27: U55.C8(DQ3) U59.AA3(DDR_D27)
DDR_D28: U55.E3(DQ4) U59.AB2(DDR_D28)
DDR_D29: U55.E8(DQ5) U59.AB1(DDR_D29)
DDR_D30: U55.D2(DQ6) U59.AC1(DDR_D30)
DDR_D31: U55.E7(DQ7) U59.AC2(DDR_D31)
DDR_DQM0: U59.F4(DDR_DQM0) U60.B7(DM)
DDR_DQM1: U58.B7(DM) U59.H2(DDR_DQM1)
DDR_DQM2: U57.B7(DM) U59.V6(DDR_DQM2)
DDR_DQM3: U55.B7(DM) U59.Y1(DDR_DQM3)
DDR_DQS0: U59.F2(DDR_DQS0) U60.C3(DQS)
DDR_DQS1: U58.C3(DQS) U59.J2(DDR_DQS1)
DDR_DQS2: U57.C3(DQS) U59.W1(DDR_DQS2)
DDR_DQS3: U55.C3(DQS) U59.AA1(DDR_DQS3)
DDR_DQSN0: U59.F1(DDR_DQS0n) U60.D3(DQSn)
DDR_DQSN1: U58.D3(DQSn) U59.J1(DDR_DQS1n)
DDR_DQSN2: U57.D3(DQSn) U59.W2(DDR_DQS2n)
DDR_DQSN3: U55.D3(DQSn) U59.AA2(DDR_DQS3n)
DDR_ODT: R323.2(P2) U55.G1(ODT) U57.G1(ODT) U58.G1(ODT) U59.U1(DDR_ODT0) U60.G1(ODT)
DDR_RASN: R88.2(P2) U55.F3(RASn) U57.F3(RASn) U58.F3(RASn) U59.N2(DDR_RASn) U60.F3(RASn)
DDR_RESETn: R141.1(P1) U55.N2(RESETn) U57.N2(RESETn) U58.N2(RESETn) U59.T1(DDR_RESETn) U60.N2(RESETn)
DDR_WEn: R315.2(P2) U55.H3(WEn) U57.H3(WEn) U58.H3(WEn) U59.N4(DDR_WEn) U60.H3(WEn)
ETH1_LDO_O: Q6.G(GATE) U41.43(LDO_O)
ETH1_RESETn: C277.1 D7.2(Anode) R239.1(P1) U41.42(RESET_N) U75.4(Y)
ETH1_RXCLK: R223.1(P1) R444.2(P2) R445.2(P2) U41.35(RX_CLK)
ETH1_RXD0: R217.1(P1) R437.2(P2) R438.2(P2) U41.32(RXD0)
ETH1_RXD1: R215.1(P1) R433.2(P2) R434.2(P2) U41.31(RXD1)
ETH1_RXD2: R212.1(P1) R431.2(P2) R432.2(P2) U41.28(RXD2)
ETH1_RXD3: R209.1(P1) R429.2(P2) R430.2(P2) U41.27(RXD3)
ETH1_RXDV: R219.1(P1) R440.2(P2) R441.2(P2) U41.33(RX_DV)
ETH1_TXCLK: R157.1(P1) U41.24(GTX_CLK)
ETH1_TXD0: R361.1(P1) U41.19(TXD0)
ETH1_TXD1: R362.1(P1) U41.20(TXD1)
ETH1_TXD2: R156.1(P1) U41.21(TXD2)
ETH1_TXD3: R154.1(P1) U41.22(TXD3)
ETH1_TXEN: R363.1(P1) U41.25(TX_EN)
ETH_MDIO_CLK: R226.2(P2) R448.2(P2) U59.B17(MDIO_CLK/MDIO_CLK)
ETH_MDIO_DATA: R230.2(P2) R451.1(P1) U59.A17(MDIO_DATA/MDIO_DATA)
ETHER1_D0N: J18.10 U41.3(TXRXM_A)
ETHER1_D0P: J18.9 U41.2(TXRXP_A)
ETHER1_D1N: J18.8 U41.6(TXRXM_B)
ETHER1_D1P: J18.7 U41.5(TXRXP_B)
ETHER1_D2N: J18.6 U41.8(TXRXM_C)
ETHER1_D2P: J18.5 U41.7(TXRXP_C)
ETHER1_D3N: J18.4 U41.11(TXRXM_D)
ETHER1_D3P: J18.3 U41.10(TXRXP_D)
GP_I2C_SCL: U47.8(B1) ; also on sheet 2 4 5 21 23 27
GP_I2C_SDA: U47.1(B2) ; also on sheet 2 4 5 21 23 27
GPIO_VTTEN: R34.2(P2) ; also on sheet 21
PHY1_LED_ACTn: J18.12 R205.2(P2) R425.2(P2) U41.17(LED1_/_PME_N1)
PHY1_LED_LINKn: J18.13 R206.2(P2) R424.2(P2) U41.15(LED2)
PM_AM437X_V1_8DN: R68.4(SENS2) ; also on sheet 20
PM_AM437X_V1_8DP: R68.3(SENS1) ; also on sheet 20
PM_AM437X_V3_3DN: R155.4(SENS2) ; also on sheet 20
PM_AM437X_V3_3DP: R155.3(SENS1) ; also on sheet 20
PM_VDDCOREN: R328.4(SENS2) ; also on sheet 20
PM_VDDCOREP: R328.3(SENS1) ; also on sheet 20
PM_VDDMPUN: R317.4(SENS2) ; also on sheet 20
PM_VDDMPUP: R317.3(SENS1) ; also on sheet 20
PM_VDDSAM437XDDRN: R305.4(SENS2) ; also on sheet 20
PM_VDDSAM437XDDRP: R305.3(SENS1) ; also on sheet 20
PM_VDDSDDRN: R307.4(SENS2) ; also on sheet 20
PM_VDDSDDRP: R307.3(SENS1) ; also on sheet 20
SENSOR_HREF: J39.17 U8.10(2B2)
SENSOR_PCLK: J39.9 U50.4(B)
SENSOR_PWDN: J39.18 R556.1(P1) R557.2(P2)
SENSOR_RESET: J39.20 R558.2(P2) U8.12(1B2)
SENSOR_SIO_C: J39.21 R552.1(P1) U47.5(A1)
SENSOR_SIO_D: J39.23 R553.1(P1) U47.4(A2)
SENSOR_VSYNC: J39.19 U8.11(2B1)
SENSOR_XCLK: J39.13 U8.13(1B1)
SENSOR_Y2: J39.7 U15.21(B1)
SENSOR_Y3: J39.5 U15.20(B2)
SENSOR_Y4: J39.4 U15.19(B3)
SENSOR_Y5: J39.6 U15.18(B4)
SENSOR_Y6: J39.8 U15.17(B5)
SENSOR_Y7: J39.10 U15.16(B6)
SENSOR_Y8: J39.12 U15.15(B7)
SENSOR_Y9: J39.14 U15.14(B8)
SYS_RESETn: U75.2(A) ; also on sheet 1 4 5 10 24
USB0_CONN_DM: J11.2(DM) L1.3 U61.2(D-)
USB0_CONN_DP: J11.3(DP) L1.4 U61.1(D+)
USB0_ID: J11.4(ID) R148.2(P2) R350.1(P1) U61.3(ID)
USB0_OVRCURn: R124.2(P2) U21.5(~{OC})
USB0_VBUS_DET: Q2.D(DRAIN) R126.1(P1) ; also on sheet 21
USB0_VBUS_EN: R146.1(P1) R151.1(P1) U21.4(EN)
VAM437X_DDR: C134.1 C136.1 C149.1 C152.1 C159.1 C161.1 C188.1 C214.1 C288.1 R305.2(I2) R492.1 U59.K7(VDD_DDR) U59.K8(VDD_DDR) U59.M7(VDD_DDR) U59.M8(VDD_DDR) U59.N7(VDD_DDR) U59.N8(VDD_DDR) U59.R6(VDD_DDR) U59.R7(VDD_DDR) U59.R8(VDD_DDR) U59.T7(VDD_DDR) U59.T8(VDD_DDR) U59.V7(VDD_DDR) U59.V8(VDD_DDR)
VCOM_BAT: C419.1 C422.1 C436.1 J20.5 J20.7 R446.2 U71.4(OUT)
VCOM_BATEN: R436.1(P1) U71.1(EN)
VCOM_BATFB: C422.2 R439.2(P2) R446.1 U71.5(FB)
VDCDC1: J31.2 R328.1(I1) ; also on sheet 20 23
VDCDC2: J28.2 R317.1(I1) ; also on sheet 20 23
VDCDC3: R307.1(I1) ; also on sheet 23
VETH1_AVDDH: C262.1 C263.1 C415.1 FB10.2 Q6.S(SOURCE) U41.1(AVDDH) U41.12(AVDDH) U41.47(AVDDH)
VETH1_AVDDL: C270.1 C272.1 FB25.2 U41.4(AVDDL) U41.9(AVDDL)
VETH1_AVDDL_PLL: C420.1 C421.1 C425.1 FB22.2 U41.44(AVDDL_PLL)
VETH1_AVDDL_PMOS: C394.1 FB21.1 FB22.1 FB25.1 Q6.D1(DRAIN1) Q6.D2(DRAIN2)
VETH1_DVDDH: C398.1 C402.1 C426.1 D7.1(Cathode) R237.2(P2) R239.2(P2) R424.1(P1) R425.1(P1) R427.1(P1) R430.1(P1) R432.1(P1) R434.1(P1) R438.1(P1) R441.1(P1) R444.1(P1) R448.1(P1) R451.2(P2) U41.16(DVDDH) U41.34(DVDDH) U41.40(DVDDH) U75.5(VCC)
VETH1_DVDDL: C392.1 C393.1 FB21.2 U41.14(DVDDL) U41.18(DVDDL) U41.23(DVDDL) U41.26(DVDDL) U41.30(DVDDL) U41.39(DVDDL)
VLS1: R305.1(I1) ; also on sheet 23
VPP_CONN: J42.2 R639.1(P1)
VUSB_VBUS0: C198.1 C199.1 J11.1(VBUS) J12.1 Q2.G(GATE) R112.1(P1) R132.2(P2) U21.6(OUT) U21.7(OUT) U21.8(OUT) U61.6(VBUS) ; also on sheet 23
N11217419: C321.1 R54.1(P1) R55.1(P1)
N12081710: J38.1 R237.1(P1) U41.38(INT_N_/_PME_N2)
N12081804: C276.2 U41.46(XI) Y6.2
N12081808: C275.2 U41.45(XO) Y6.1
N12123192: J18.11 R423.1
N12123204: J18.14 R467.1
N12138752: R226.1(P1) U41.36(MDC)
N12138831: R230.1(P1) U41.37(MDIO)
N12138943: R231.1 U41.48(ISET)
N12139138: TP25.1 U41.41(CLK125_NDO)
N12595082: R342.2(P2) U59.AC3(DDR_VTP)
N15715520: R457.1(P1) U59.A12(GPMC_CLK/MMC2_CLK)
N15715532: R456.1(P1) U59.B12(GPMC_CSN3/MMC2_CMD)
N15715544: R455.1(P1) U59.C5(GPMC_A1/MMC2_DAT0)
N15715556: R454.1(P1) U59.C6(GPMC_A2/MMC2_DAT1)
N15715568: R453.1(P1) U59.A4(GPMC_A3/MMC2_DAT2)
N15715580: R452.1(P1) U59.A3(GPMC_BE1n/MMC2_DAT3)
N15715840: R251.1(P1) U59.F7(GPMC_A8/MCASP0_ACLKX)
N15715852: R253.1(P1) U59.G8(GPMC_A10/MCASP0_AXR0)
N15715864: R254.1(P1) U59.D8(GPMC_A11/MCASP0_AXR1)
N15717058: R252.1(P1) U59.B4(GPMC_A9/MCASP0_FSX)
N15717194: U33.13(1B1) U59.H24(UART3_TXD)
N15717226: U33.11(2B1) U59.H25(UART3_RXD)
N15717266: U33.10(2B2) U59.H22(UART3_CTSn)
N15717730: R490.2(P2) U34.3(A)
N15781308: R133.2(P2) U60.H8(ZQ)
N15810701: R110.2(P2) U58.H8(ZQ)
N15813652: R94.2(P2) U57.H8(ZQ)
N15822328: R34.1(P1) R35.2(P2) U4.7(EN)
N15822442: R36.1(P1) U4.9(PGOOD)
N15822464: C21.1 R43.1(P1) U4.5(VOSNS)
N15822844: C20.1 R39.2(P2) R41.1(P1) U4.1(REFIN)
N15826249: R62.2(P2) U55.H8(ZQ)
N16755717: R255.1(P1) U33.6(2A1)
N16755735: R256.1(P1) U33.4(1A1)
N16755741: R257.1(P1) U33.5(1A2)
N16755753: R258.1(P1) U33.7(2A2)
N16756587: U34.4(B) U59.C24(XDMA_EVENT_INTR1/CLKOUT2)
N17462072: C292.1 FB6.2 U59.E23(VDDS_CLKOUT)
N17463583: TP22.1 U59.D20(VDD_MPU_MON)
N17515933: R151.2(P2) U59.G21(USB0_DRVVBUS)
N17571259: R60.2(P2) U8.14(2~{OE}) U8.15(1~{OE}) U15.22(~{OE})
N17572398: R288.1(P1) U47.6(OE)
N17573154: C329.1 U54.4(NR)
N17670442: R111.2(P2) U59.AA23(TEST_EN)
N17688718: C473.1 R639.2(P2) U59.P21(VPP)
N17695349: C110.1 R333.1(P1) U59.AD3(CAP_VDD_RTC)
N17746486: R189.2(P2) U34.5(DIR)
N17747795: R195.2(P2) U33.2(1DIR)
N17748019: R196.2(P2) U33.3(2DIR)
N17748257: U33.12(1B2) U59.K24(UART3_RTSn)
N19385841: J42.4 R638.1(P1) R640.2(P2)

Not connected (* = marked no-connect by the designer): J18 2; J20 10 12 14 16 17 21 23 25 27 29 31 33 36 38 40 41 43 44 45 46 49 51 53 55 57 59 61 65 67 69 71 73 74 75 78 79 80 81 82 84 85 86 88 90 91 93 94 96 98 99 100; J39 1* 2* 3* 16* 25*; R159 2(P2)*; SCKT1 MCH1* MCH2* MCH3* MCH4*; U55 A3(NU) A7(NF/TDQS#) F1(NU) F9(NU) H1(NU) H9(NU); U57 A3(NU) A7(NF/TDQS#) F1(NU) F9(NU) H1(NU) H9(NU); U58 A3(NU) A7(NF/TDQS#) F1(NU) F9(NU) H1(NU) H9(NU); U59 H21(TESTOUT) M4(DDR_CSN1) N6(DDR_CKE1) U2(DDR_ODT1); U60 A3(NU)* A7(NF/TDQS#) F1(NU)* F9(NU)* H1(NU)* H9(NU)*; U61 5(NC)*; U75 1(NC)

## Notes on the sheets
sheet 13
- ARM MPU AM4378 General Purpose EVM
- -See the Hardware User Guide for board details
- -See the Errata document for the board for details
- -See the PCB Build Specification for PCB Details
sheet 16
- USB0 Port
